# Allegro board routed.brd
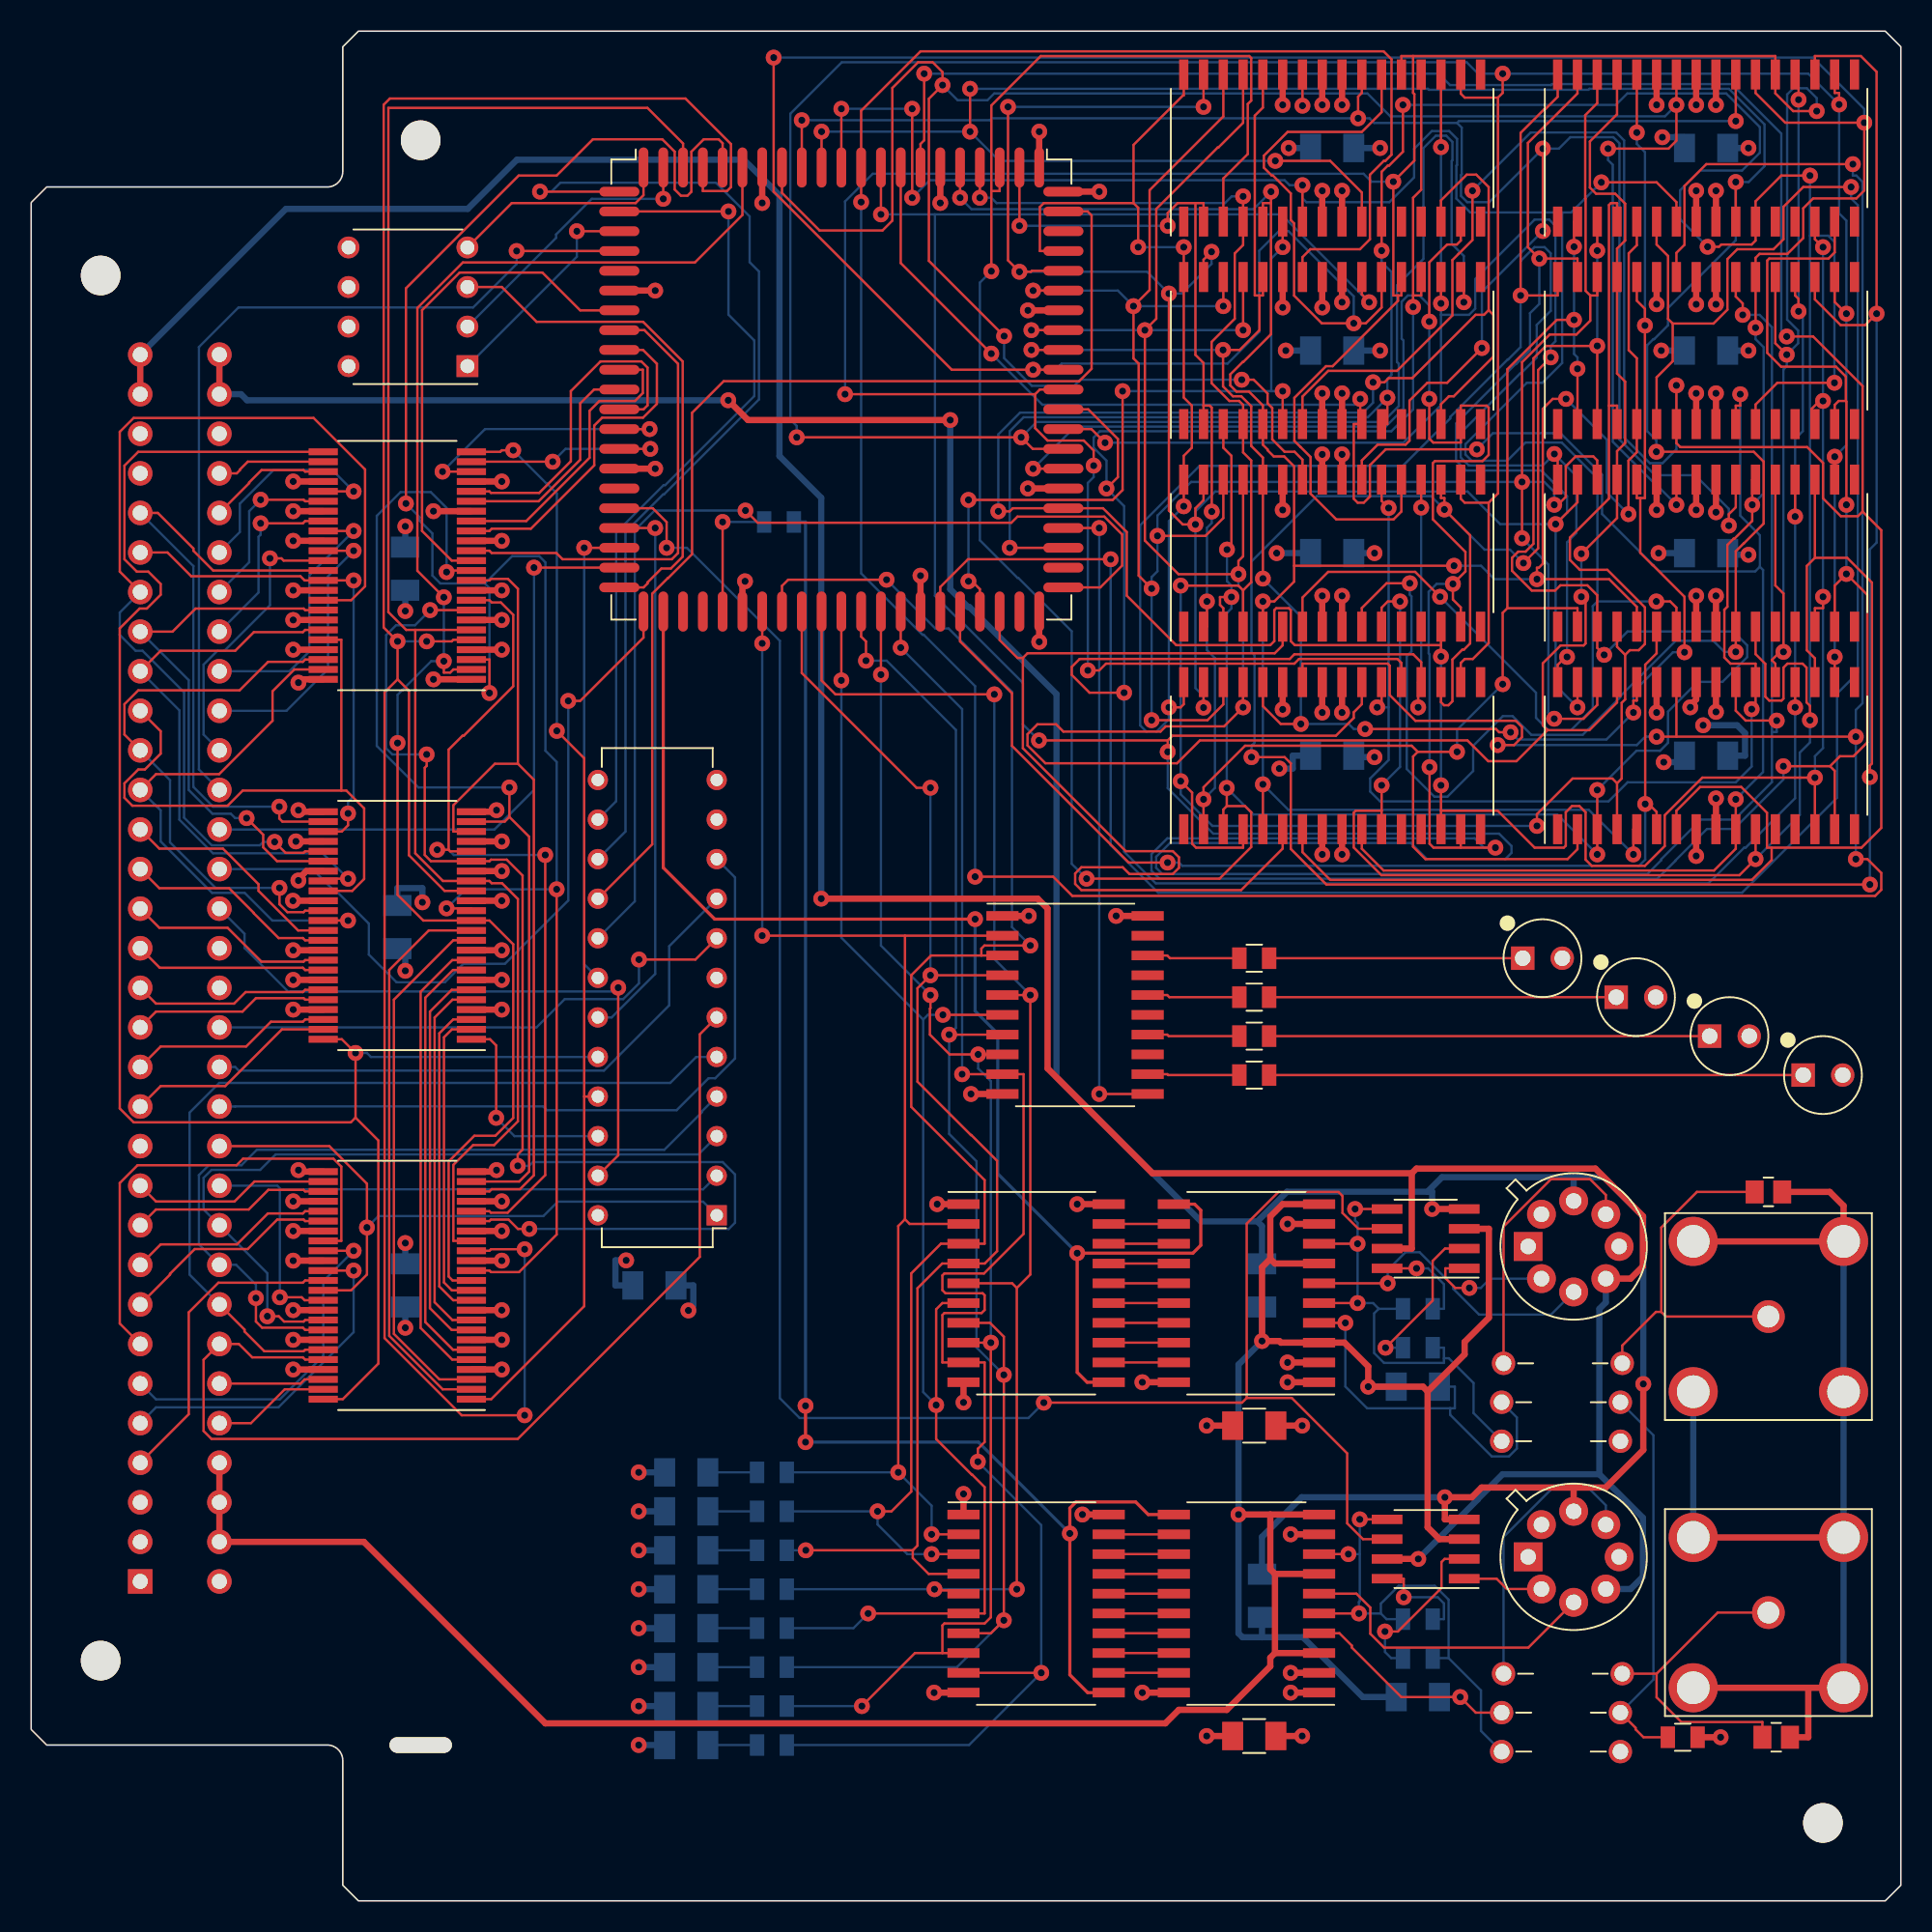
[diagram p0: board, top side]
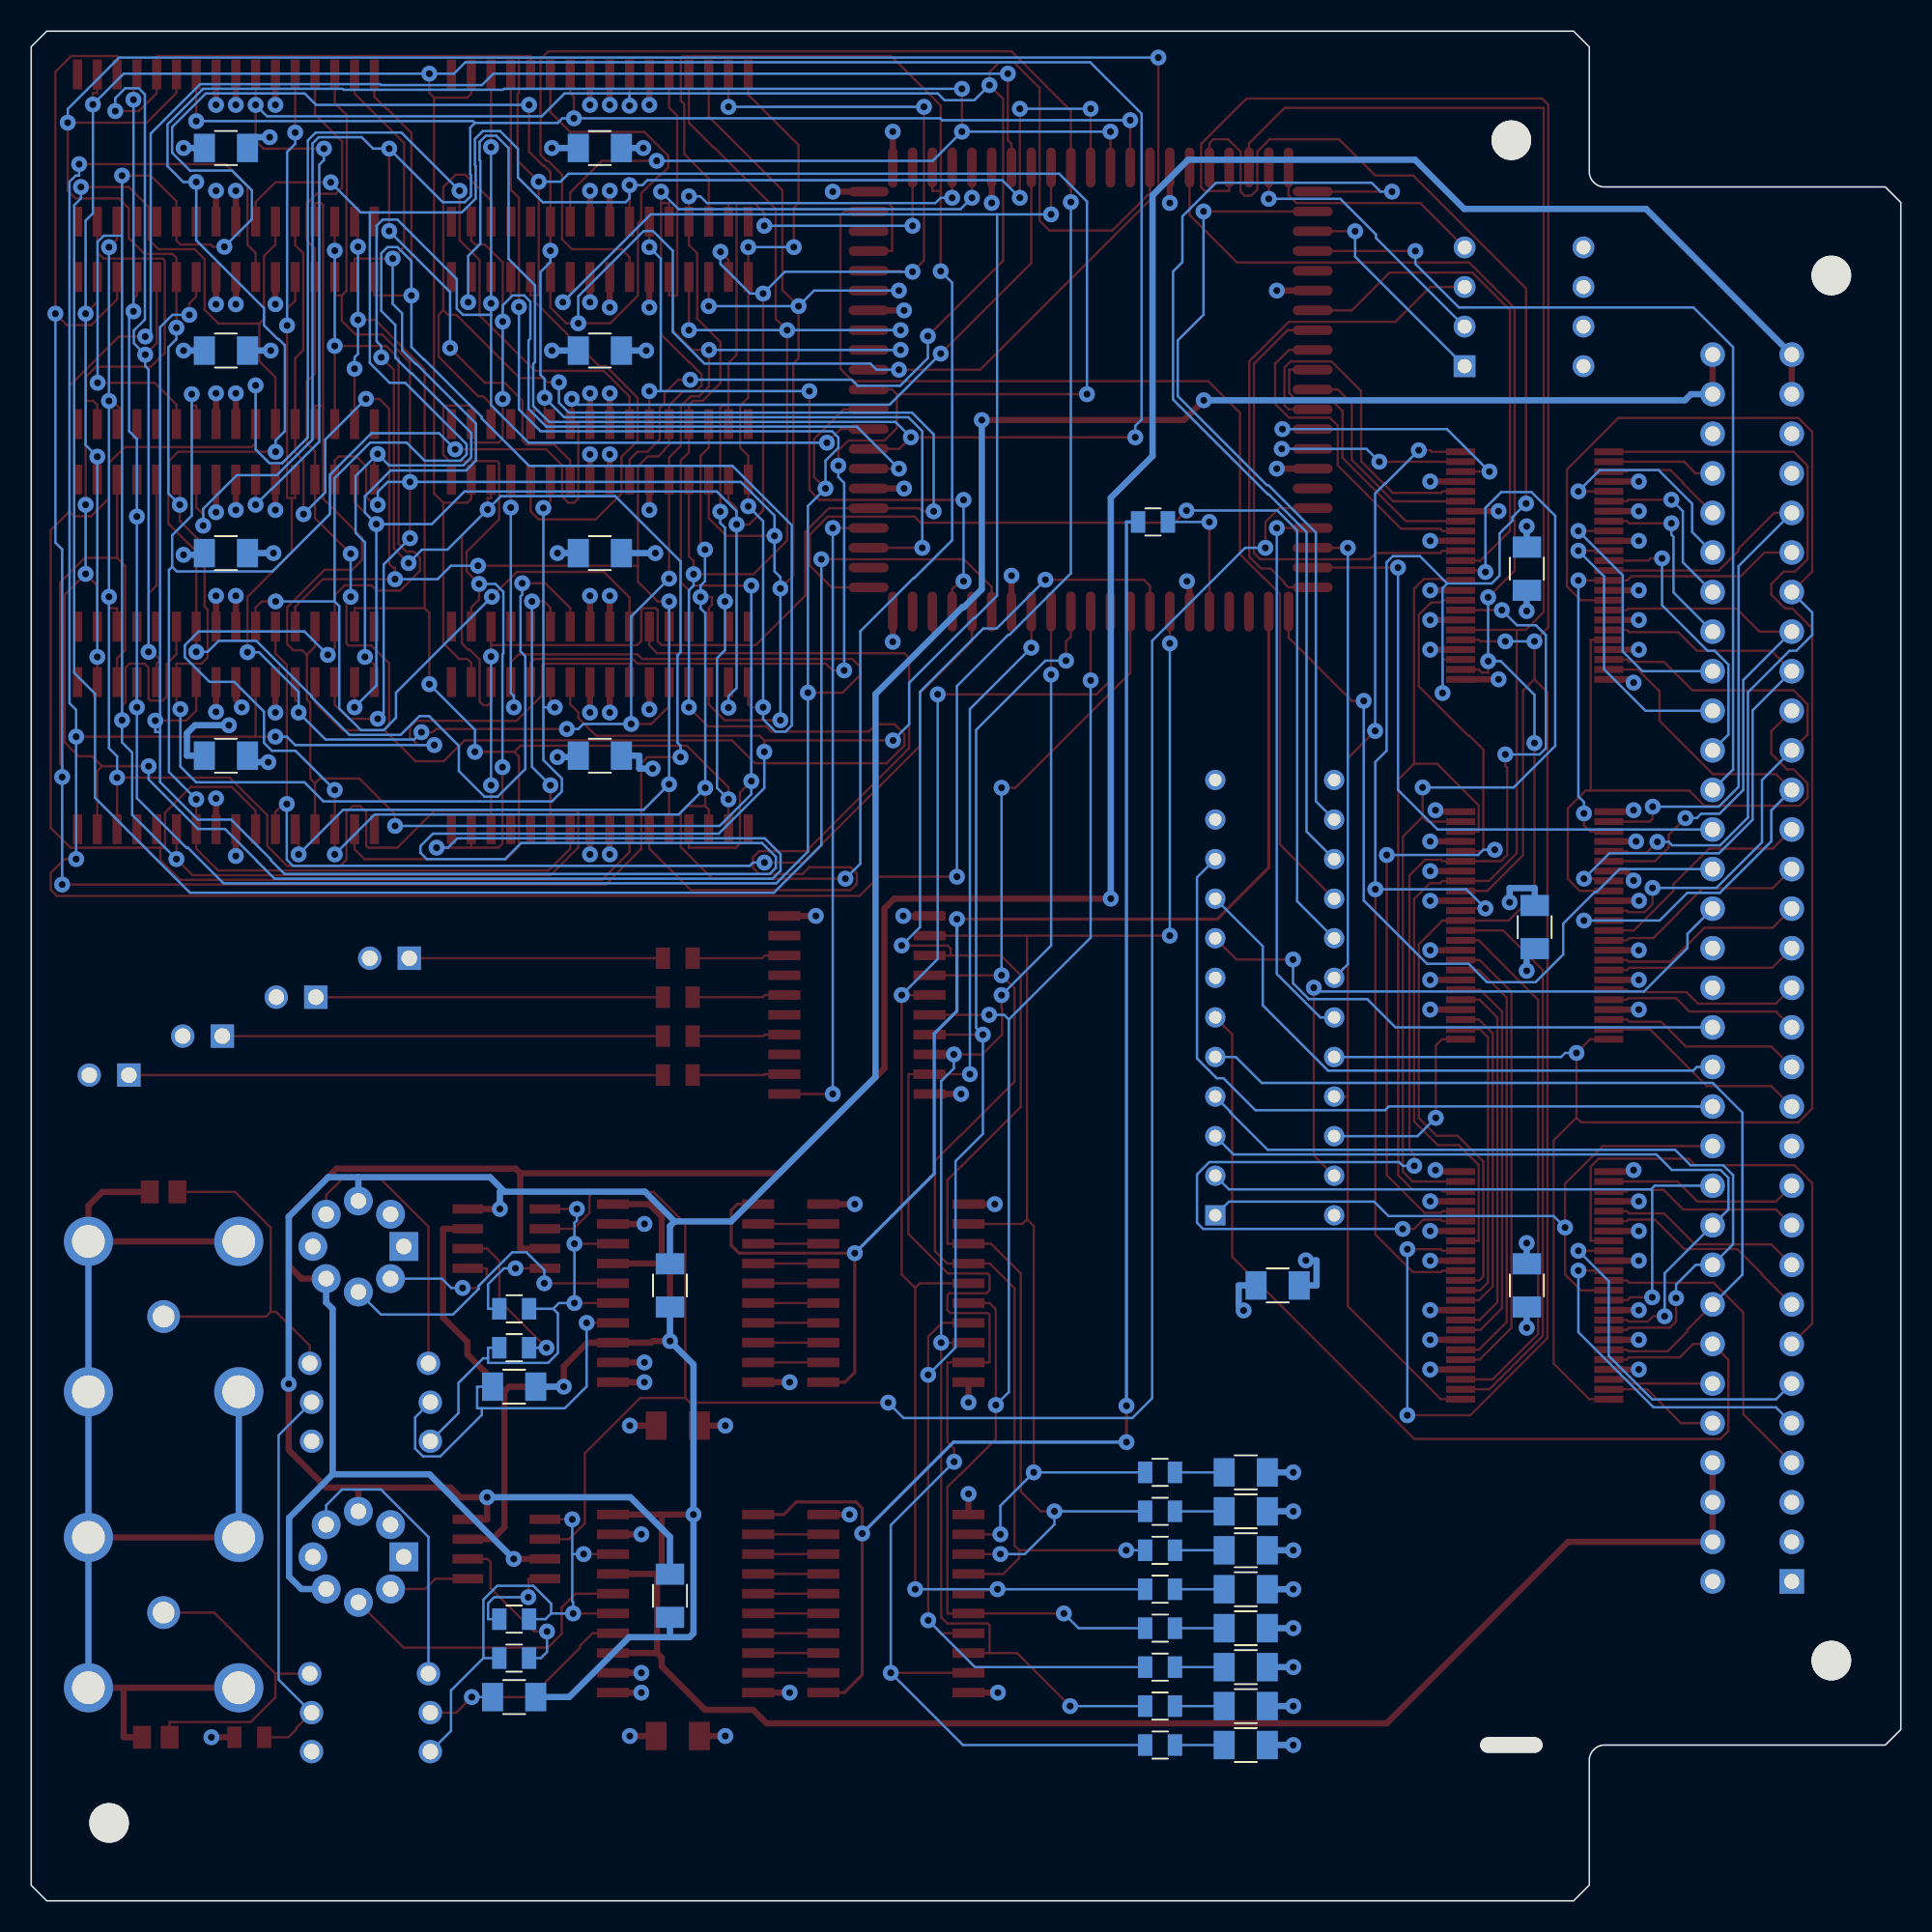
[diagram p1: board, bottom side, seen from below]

Outline 120 x 120 mm; copper layers: TOP, GND1, VCC1, VCC2, GND2, BOTTOM. Coordinates in mm from the lower left corner of the outline.

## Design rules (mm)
constraint set DEFAULT: min track width 0.15
net group SYNC: nets VCLKA VCLKC
net group MEMORY[0..28]: nets MEMORY.RA0 MEMORY.RA1 MEMORY.RA2 MEMORY.RA3 MEMORY.RA4 MEMORY.RA5 MEMORY.RA6 MEMORY.RA7 MEMORY.RA8 MEMORY.RA9 MEMORY.RA10 MEMORY.RA11 MEMORY.RA12 MEMORY.RA13 MEMORY.RA14 MEMORY.RA15 MEMORY.RCS0 MEMORY.RCS1 MEMORY.RCS2 MEMORY.RCS3 MEMORY.RD0 MEMORY.RD1 MEMORY.RD2 MEMORY.RD3 MEMORY.RD4 MEMORY.RD5 MEMORY.RD6 MEMORY.RD7 MEMORY.RWE
net group POWER: nets AGND GND_EARTH V12N V+12
net group VDNETS: nets VD0 VD1 VD2 VD3 VD4 VD5 VD6 VD7
nets with their own width: min track width 0.4; nets GND VCC

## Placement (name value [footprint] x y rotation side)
C1  0.1uF  [CAPC3216X110N]  24 39.5 90 bottom
C2  0.1uF  [CAPC3216X110N]  40 39.5 0 bottom
C3  0.1uF  [CAPC3216X110N]  23.5 62.5 90 bottom
C4  0.1uF  [CAPC3216X110N]  24 85.5 90 bottom
C5  47PF  [CAPC2012X110N]  111.5 45.5 0 top
C6  47PF  [CAPC2012X110N]  112 10.5 0 top
C7  0.01u  [CAPC3216X110N]  78.5 30.5 0 top
C8  0.01u  [CAPC3216X110N]  89 33 180 bottom
C9  0.1u  [CAPC3216X110N]  79 39.5 270 bottom
C10  0.01u  [CAPC3216X110N]  78.5 10.58 0 top
C11  0.01u  [CAPC3216X110N]  89 13.08 180 bottom
C12  0.1u  [CAPC3216X110N]  79 19.58 270 bottom
C13  330p  [CAPC3216X110N]  42.05 12.5 180 bottom
C14  330p  [CAPC3216X110N]  42.05 17.5 180 bottom
C15  330p  [CAPC3216X110N]  42.05 22.5 180 bottom
C16  330p  [CAPC3216X110N]  42.05 27.5 180 bottom
C17  330p  [CAPC3216X110N]  42.05 10 180 bottom
C18  330p  [CAPC3216X110N]  42.05 15 180 bottom
C19  330p  [CAPC3216X110N]  42.05 20 180 bottom
C20  330p  [CAPC3216X110N]  42.05 25 180 bottom
C21  0.1uF  [CAPC3216X110N]  83.5 112.5 0 bottom
C22  0.1uF  [CAPC3216X110N]  83.5 99.5 0 bottom
C23  0.1uF  [CAPC3216X110N]  83.5 86.5 0 bottom
C24  0.1uF  [CAPC3216X110N]  83.5 73.5 0 bottom
C25  0.1uF  [CAPC3216X110N]  107.5 73.5 0 bottom
C26  0.1uF  [CAPC3216X110N]  107.5 86.5 0 bottom
C27  0.1uF  [CAPC3216X110N]  107.5 112.5 0 bottom
C28  0.1uF  [CAPC3216X110N]  107.5 99.5 0 bottom
D1  LED  [LEDRD254W00D500H860P]  97 60.5 0 top
D2  LED  [LEDRD254W00D500H860P]  103 58 0 top
D3  LED  [LEDRD254W00D500H860P]  109 55.5 0 top
D4  LED  [LEDRD254W00D500H860P]  115 53 0 top
J1  CON64  [DIN64]  7 20.5 0 top
J2  BNC  [CONNEX_112659]  111.5 37.5 0 top
J3  BNC  [CONNEX_112659]  111.5 18.5 0 top
L1  47u  [INDAD762W79L381D254P]  94.5 34.5 0 top
L2  47u  [INDAD762W79L381D254P]  94.5 14.58 0 top
L3  47u  [INDAD762W79L381D254P]  102 32 180 top
L4  47u  [INDAD762W79L381D254P]  102 29.5 180 top
L5  47u  [INDAD762W79L381D254P]  102 12.08 180 top
L6  47u  [INDAD762W79L381D254P]  102 9.58 180 top
NOREF  -  []  19.76 110.35 0 top
NOREF#2  -  []  119.43 119.57 0 top
NOREF#3  -  []  25 10 90 top
NOREF#4  -  []  -71.52 -89.06 0 top
NOREF#5  -  []  20 4.47 0 top
NOREF#6  -  []  25 10 90 top
NOREF#7  -  []  25 10 0 top
NOREF#8  -  [unnamed#2]  25 10 0 top
NOREF#9  -  []  25 10 0 top
NOREF#10  -  []  0 15.3 0 top
NOREF#11  -  []  25.27 0 90 top
NOREF#12  -  []  197.72 152.24 0 top
NOREF#13  -  []  25 10 90 top
R1  150  [RESC2012X60N]  78.5 60.5 0 top
R2  150  [RESC2012X60N]  78.5 58 0 top
R3  150  [RESC2012X60N]  78.5 55.5 0 top
R4  150  [RESC2012X60N]  78.5 53 0 top
R5  2K  [RESC2012X60N]  48 88.5 0 bottom
R6  100  [RESC2012X60N]  89 38 0 bottom
R7  100  [RESC2012X60N]  89 35.5 180 bottom
R8  100  [RESC2012X60N]  89 18.08 0 bottom
R9  100  [RESC2012X60N]  89 15.58 180 bottom
R10  10K  [RESC2012X60N]  47.55 12.5 0 bottom
R11  10K  [RESC2012X60N]  47.55 17.5 0 bottom
R12  10K  [RESC2012X60N]  47.55 22.5 0 bottom
R13  10K  [RESC2012X60N]  47.55 27.5 0 bottom
R14  10K  [RESC2012X60N]  47.55 10 0 bottom
R15  10K  [RESC2012X60N]  47.55 15 0 bottom
R16  10K  [RESC2012X60N]  47.55 20 0 bottom
R17  10K  [RESC2012X60N]  47.55 25 0 bottom
R18  10K  [RESC2012X60N]  106 10.5 0 top
U1  FCT16245  [SOP63P1035X279-48N]  23.5 39.5 90 top
U2  20L10  [DIP763W46P254L3204H508Q24P]  44 44 90 top
U3  FCT16245  [SOP63P1035X279-48N]  23.5 62.6 90 top
U4  FCT16245  [SOP63P1035X279-48N]  23.5 85.7 90 top
U5  EPF8282A_LCC  [PLCC127P3022X3022X457-84N]  52 97 270 top
U6  74ACT574  [SOIC127P1034X264-20N]  67 57.5 270 top
U7  EPC1064  [DIP763W46P254L991H419Q8P]  28 98.5 90 top
U8  TLC5602A  [SOIC127P1034X264-20N]  78 39 90 top
U9  TLE2037A  [TO292P469H584-8P]  99 42 0 top
U10  DG419AK  [SOIC127P600X175-8N]  89.5 42.5 90 top
U11  TLC5602A  [SOIC127P1034X264-20N]  78 19.08 90 top
U12  TLE2037A  [TO292P469H584-8P]  99 22.08 0 top
U13  DG419AK  [SOIC127P600X175-8N]  89.5 22.58 90 top
U14  74ACT574  [SOIC127P1034X264-20N]  64.5 39 270 top
U15  74ACT574  [SOIC127P1034X264-20N]  64.5 19.08 270 top
U16  TC55B4257  [SOIC127P1032X265-32N]  83.5 73.5 0 top
U17  TC55B4257  [SOIC127P1032X265-32N]  83.5 86.5 0 top
U18  TC55B4257  [SOIC127P1032X265-32N]  83.5 99.5 0 top
U19  TC55B4257  [SOIC127P1032X265-32N]  83.5 112.5 0 top
U20  TC55B4257  [SOIC127P1032X265-32N]  107.5 73.5 0 top
U21  TC55B4257  [SOIC127P1032X265-32N]  107.5 86.5 0 top
U22  TC55B4257  [SOIC127P1032X265-32N]  107.5 99.5 0 top
U23  TC55B4257  [SOIC127P1032X265-32N]  107.5 112.5 0 top

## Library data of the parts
C1-C4 C13-C20 = CAP NP
C5 C7-C9 = CAP NP: room: CHAN1
C6 C10-C12 = CAP NP: room: CHAN2
C21-C28 = CAP NP: room: MEM
D1-D4 = PHOTODIODE_0
J1 = CON64
J2 = BNC: room: CHAN1
J3 = BNC: room: CHAN2
L1 L3 L4 = INDUCTOR: room: CHAN1
L2 L5 L6 = INDUCTOR: room: CHAN2
R1-R4 = R: room: LED
R5 R10-R17 = R
R6 R7 = R: room: CHAN1
R8 R9 R18 = R: room: CHAN2
U1 U3 U4 = FCT16245
U2 = 20L10: alternate symbols: (T:SOIC24;B:SOIC24_PE)
U5 = EPF8282A/LCC
U6 = 74ACT574: room: LED
U7 = EPC1064
U8 = TLC5602A: room: CHAN1
U9 = TLE2037A: room: CHAN1
U10 = DG419AK: room: CHAN1
U11 = TLC5602A: room: CHAN2
U12 = TLE2037A: room: CHAN2
U13 = DG419AK: room: CHAN2
U14 = 74ACT574: room: CHAN1
U15 = 74ACT574: room: CHAN2
U16-U23 = TC55B4257: room: MEM

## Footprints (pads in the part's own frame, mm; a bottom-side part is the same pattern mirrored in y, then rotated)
CAPC2012X110N
  rect 1.15x1.47 smd: 1(-0.885,0) 2(0.885,0)
CAPC3216X110N
  rect 1.35x1.82 smd: 1(-1.385,0) 2(1.385,0)
CONNEX_112659
  round 2.1 hole 1.4: 1(0,0)
  round 3.15 hole 2.1: 2(-4.825,4.825) 3(4.825,4.825) 4(4.825,-4.825) 5(-4.825,-4.825)
DIN64
  round 2.54 hole 2.794 unplated: (-2.54,83.82) (-2.54,-5.08)
  rect 1.575x1.575 hole 0.965: 1(0,0)
  round 1.575 hole 0.965: 2(0,2.54) 3(0,5.08) 4(0,7.62) 5(0,10.16) 6(0,12.7) 7(0,15.24) 8(0,17.78) 9(0,20.32) 10(0,22.86) 11(0,25.4) 12(0,27.94) 13(0,30.48) 14(0,33.02) 15(0,35.56) 16(0,38.1) 17(0,40.64) 18(0,43.18) 19(0,45.72) 20(0,48.26) 21(0,50.8) 22(0,53.34) 23(0,55.88) 24(0,58.42) 25(0,60.96) 26(0,63.5) 27(0,66.04) 28(0,68.58) 29(0,71.12) 30(0,73.66) 31(0,76.2) 32(0,78.74) 33(5.08,0) 34(5.08,2.54) 35(5.08,5.08) 36(5.08,7.62) 37(5.08,10.16) 38(5.08,12.7) 39(5.08,15.24) 40(5.08,17.78) 41(5.08,20.32) 42(5.08,22.86) 43(5.08,25.4) 44(5.08,27.94) 45(5.08,30.48) 46(5.08,33.02) 47(5.08,35.56) 48(5.08,38.1) 49(5.08,40.64) 50(5.08,43.18) 51(5.08,45.72) 52(5.08,48.26) 53(5.08,50.8) 54(5.08,53.34) 55(5.08,55.88) 56(5.08,58.42) 57(5.08,60.96) 58(5.08,63.5) 59(5.08,66.04) 60(5.08,68.58) 61(5.08,71.12) 62(5.08,73.66) 63(5.08,76.2) 64(5.08,78.74)
DIP763W46P254L991H419Q8P
  rect 1.4x1.4 hole 0.9: 1(0,0)
  round 1.4 hole 0.9: 2(2.54,0) 3(5.08,0) 4(7.62,0) 5(7.62,7.63) 6(5.08,7.63) 7(2.54,7.63) 8(0,7.63)
DIP763W46P254L3204H508Q24P
  rect 1.3x1.3 hole 0.8: 1(0,0)
  round 1.3 hole 0.8: 2(2.54,0) 3(5.08,0) 4(7.62,0) 5(10.16,0) 6(12.7,0) 7(15.24,0) 8(17.78,0) 9(20.32,0) 10(22.86,0) 11(25.4,0) 12(27.94,0) 13(27.94,7.63) 14(25.4,7.63) 15(22.86,7.63) 16(20.32,7.63) 17(17.78,7.63) 18(15.24,7.63) 19(12.7,7.63) 20(10.16,7.63) 21(7.62,7.63) 22(5.08,7.63) 23(2.54,7.63) 24(0,7.63)
INDAD762W79L381D254P
  round 1.5 hole 1: 1(0,0) 2(7.62,0)
LEDRD254W00D500H860P
  round 1.5 hole 1: A(1.27,0)
  rect 1.5x1.5 hole 1: C(-1.27,0)
PLCC127P3022X3022X457-84N
  oval 2.57x0.62 smd: 1(-14.25,0) 2(-14.25,-1.27) 3(-14.25,-2.54) 4(-14.25,-3.81) 5(-14.25,-5.08) 6(-14.25,-6.35) 7(-14.25,-7.62) 8(-14.25,-8.89) 9(-14.25,-10.16) 10(-14.25,-11.43) 11(-14.25,-12.7) 33(14.25,-12.7) 34(14.25,-11.43) 35(14.25,-10.16) 36(14.25,-8.89) 37(14.25,-7.62) 38(14.25,-6.35) 39(14.25,-5.08) 40(14.25,-3.81) 41(14.25,-2.54) 42(14.25,-1.27) 43(14.25,0) 44(14.25,1.27) 45(14.25,2.54) 46(14.25,3.81) 47(14.25,5.08) 48(14.25,6.35) 49(14.25,7.62) 50(14.25,8.89) 51(14.25,10.16) 52(14.25,11.43) 53(14.25,12.7) 75(-14.25,12.7) 76(-14.25,11.43) 77(-14.25,10.16) 78(-14.25,8.89) 79(-14.25,7.62) 80(-14.25,6.35) 81(-14.25,5.08) 82(-14.25,3.81) 83(-14.25,2.54) 84(-14.25,1.27)
  oval 0.62x2.57 smd: 12(-12.7,-14.25) 13(-11.43,-14.25) 14(-10.16,-14.25) 15(-8.89,-14.25) 16(-7.62,-14.25) 17(-6.35,-14.25) 18(-5.08,-14.25) 19(-3.81,-14.25) 20(-2.54,-14.25) 21(-1.27,-14.25) 22(0,-14.25) 23(1.27,-14.25) 24(2.54,-14.25) 25(3.81,-14.25) 26(5.08,-14.25) 27(6.35,-14.25) 28(7.62,-14.25) 29(8.89,-14.25) 30(10.16,-14.25) 31(11.43,-14.25) 32(12.7,-14.25) 54(12.7,14.25) 55(11.43,14.25) 56(10.16,14.25) 57(8.89,14.25) 58(7.62,14.25) 59(6.35,14.25) 60(5.08,14.25) 61(3.81,14.25) 62(2.54,14.25) 63(1.27,14.25) 64(0,14.25) 65(-1.27,14.25) 66(-2.54,14.25) 67(-3.81,14.25) 68(-5.08,14.25) 69(-6.35,14.25) 70(-7.62,14.25) 71(-8.89,14.25) 72(-10.16,14.25) 73(-11.43,14.25) 74(-12.7,14.25)
RESC2012X60N
  rect 0.92x1.38 smd: 1(-0.955,0) 2(0.955,0)
SOIC127P600X175-8N
  rect 0.6x1.97 smd: 1(-1.905,-2.475) 2(-0.635,-2.475) 3(0.635,-2.475) 4(1.905,-2.475) 5(1.905,2.475) 6(0.635,2.475) 7(-0.635,2.475) 8(-1.905,2.475)
SOIC127P1032X265-32N
  rect 0.59x1.92 smd: 1(-9.525,-4.72) 2(-8.255,-4.72) 3(-6.985,-4.72) 4(-5.715,-4.72) 5(-4.445,-4.72) 6(-3.175,-4.72) 7(-1.905,-4.72) 8(-0.635,-4.72) 9(0.635,-4.72) 10(1.905,-4.72) 11(3.175,-4.72) 12(4.445,-4.72) 13(5.715,-4.72) 14(6.985,-4.72) 15(8.255,-4.72) 16(9.525,-4.72) 17(9.525,4.72) 18(8.255,4.72) 19(6.985,4.72) 20(5.715,4.72) 21(4.445,4.72) 22(3.175,4.72) 23(1.905,4.72) 24(0.635,4.72) 25(-0.635,4.72) 26(-1.905,4.72) 27(-3.175,4.72) 28(-4.445,4.72) 29(-5.715,4.72) 30(-6.985,4.72) 31(-8.255,4.72) 32(-9.525,4.72)
SOIC127P1034X264-20N
  rect 0.61x2.06 smd: 1(-5.715,-4.66) 2(-4.445,-4.66) 3(-3.175,-4.66) 4(-1.905,-4.66) 5(-0.635,-4.66) 6(0.635,-4.66) 7(1.905,-4.66) 8(3.175,-4.66) 9(4.445,-4.66) 10(5.715,-4.66) 11(5.715,4.66) 12(4.445,4.66) 13(3.175,4.66) 14(1.905,4.66) 15(0.635,4.66) 16(-0.635,4.66) 17(-1.905,4.66) 18(-3.175,4.66) 19(-4.445,4.66) 20(-5.715,4.66)
SOP63P1035X279-48N
  rect 0.44x1.87 smd: 1(-7.302,-4.755) 2(-6.668,-4.755) 3(-6.032,-4.755) 4(-5.398,-4.755) 5(-4.762,-4.755) 6(-4.128,-4.755) 7(-3.492,-4.755) 8(-2.858,-4.755) 9(-2.222,-4.755) 10(-1.588,-4.755) 11(-0.952,-4.755) 12(-0.318,-4.755) 13(0.318,-4.755) 14(0.952,-4.755) 15(1.588,-4.755) 16(2.222,-4.755) 17(2.858,-4.755) 18(3.492,-4.755) 19(4.128,-4.755) 20(4.762,-4.755) 21(5.398,-4.755) 22(6.032,-4.755) 23(6.668,-4.755) 24(7.302,-4.755) 25(7.302,4.755) 26(6.668,4.755) 27(6.032,4.755) 28(5.398,4.755) 29(4.762,4.755) 30(4.128,4.755) 31(3.492,4.755) 32(2.858,4.755) 33(2.222,4.755) 34(1.588,4.755) 35(0.952,4.755) 36(0.318,4.755) 37(-0.318,4.755) 38(-0.952,4.755) 39(-1.588,4.755) 40(-2.222,4.755) 41(-2.858,4.755) 42(-3.492,4.755) 43(-4.128,4.755) 44(-4.762,4.755) 45(-5.398,4.755) 46(-6.032,4.755) 47(-6.668,4.755) 48(-7.302,4.755)
TO292P469H584-8P
  rect 1.85x1.85 hole 1: 1(-2.921,0)
  round 1.85 hole 1: 2(-2.066,-2.066) 3(0,-2.921) 4(2.066,-2.066) 5(2.921,0) 6(2.066,2.066) 7(0,2.921) 8(-2.066,2.066)
unnamed#2
  round 2.54 hole 2.794 unplated: (0,103) (90,-5)
  oval 4x1 hole 5x1.5 unplated: (0,0)

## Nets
AGND: C8.2 C9.2 C11.2 C12.2 J1.34 J1.35 J1.36 U8.3 U8.7 U8.10 U10.3 U11.3 U11.7 U11.10 U13.3
GND: C1.2 C2.2 C3.2 C4.2 C7.2 C10.2 C13.2 C14.2 C15.2 C16.2 C17.2 C18.2 C19.2 C20.2 C21.2 C22.2 C23.2 C24.2 C25.2 C26.2 C27.2 C28.2 J1.1 J1.2 J1.3 J1.33 R18.2 U1.4 U1.10 U1.15 U1.21 U1.24 U1.25(G\) U1.28 U1.34 U1.39 U1.45 U2.11 U2.12 U2.13 U3.4 U3.10 U3.15 U3.21 U3.24 U3.25(G\) U3.28 U3.34 U3.39 U3.45 U4.1 U4.4 U4.10 U4.15 U4.21 U4.28 U4.34 U4.39 U4.45 U4.48 U5.5 U5.26 U5.47 U5.53 U5.68 U5.74 U5.75 U6.1 U6.10 U7.5 U8.1 U8.20 U11.1 U11.20 U14.1 U14.10 U15.1 U15.10 U16.9 U16.25 U16.27 U17.9 U17.25 U17.27 U18.9 U18.25 U18.27 U19.9 U19.25 U19.27 U20.9 U20.25 U20.27 U21.9 U21.25 U21.27 U22.9 U22.25 U22.27 U23.9 U23.25 U23.27
GND_EARTH: C5.2 C6.2 J2.2 J2.3 J2.4 J2.5(GND5) J3.2 J3.3 J3.4 J3.5(GND5)
V12N: J1.31 J1.32 U9.4(V-) U10.7 U12.4(V-) U13.7
VCC: C1.1 C2.1 C3.1 C4.1 C7.1 C10.1 C21.1 C22.1 C23.1 C24.1 C25.1 C26.1 C27.1 C28.1 D1.A D2.A D3.A D4.A J1.29 J1.30 J1.62 L4.1 L6.1 U1.7 U1.18 U1.31 U1.42 U2.24(VCC) U3.7 U3.18 U3.31 U3.42 U4.7 U4.18 U4.31 U4.42 U5.17 U5.38 U5.59 U5.80 U6.20 U7.7 U7.8 U8.2 U8.9(VD2) U11.2 U11.9(VD2) U14.20 U15.20 U16.8 U16.24 U17.8 U17.24 U18.8 U18.24 U19.8 U19.24 U20.8 U20.24 U21.8 U21.24 U22.8 U22.24 U23.8 U23.24
A0: J1.54 U4.36
A1: J1.55 U4.35
A2: J1.56 U4.33
A3: J1.57 U4.32
A4: J1.58 U4.30
A5: J1.59 U4.29
A6: J1.60 U4.27
A7: J1.61 U4.26
A8: J1.13 U3.47
A9: J1.14 U3.46
A10: J1.15 U3.44
A11: J1.16 U3.43
A12: J1.17 U3.41
A13: J1.18 U3.40
A14: J1.19 U3.38
A15: J1.20 U3.37
A16: J1.37 U1.47
A17: J1.38 U1.46
A18: J1.39 U1.44 U2.6
A19: J1.40 U1.43 U2.5
A20: J1.41 U1.41 U2.4
A21: J1.42 U1.40 U2.3
A22: J1.43 U1.38 U2.2
A23: J1.44 U1.37 U2.1
AEN: J1.47 U2.8
BA0: U1.13 U3.13 U4.2 U5.6
BA1: U1.14 U3.14 U4.3 U5.7
BA2: U1.16 U3.16 U4.5 U5.8
BA3: U1.17 U3.17 U4.6 U5.9
BA4: U1.19 U3.19 U4.8
BA5: U1.20 U3.20 U4.9
BA6: U1.22 U3.22 U4.11
BA7: U1.23 U3.23 U4.12
BD0: U4.23 U5.25
BD1: U4.22 U5.24
BD2: U4.20 U5.23
BD3: U4.19 U5.22
BD4: U4.17 U5.21
BD5: U4.16 U5.20
BD6: U4.14 U5.19
BD7: U4.13 U5.18
BD8: U1.12 U3.2
BD9: U1.11 U3.3
BD10: U1.9 U3.5
BD11: U1.8 U3.6
BD12: U1.6 U3.8
BD13: U1.5 U3.9
BD14: U1.3 U3.11
BD15: U1.2 U3.12
BNC2: C5.1 J2.1 L1.2
BNC3: C6.1 J3.1 L2.2
BRD: U2.16 U5.73
BRESET: U2.15 U5.12
BWR: U2.17 U5.54
D0: J1.28 U3.26 U4.37
D1: J1.27 U3.27 U4.38
D2: J1.26 U3.29 U4.40
D3: J1.25 U3.30 U4.41
D4: J1.24 U3.32 U4.43
D5: J1.23 U3.33 U4.44
D6: J1.22 U3.35 U4.46
D7: J1.21 U3.36 U4.47
D8: J1.4 U1.36
D9: J1.5 U1.35
D10: J1.6 U1.33
D11: J1.7 U1.32
D12: J1.8 U1.30
D13: J1.9 U1.29
D14: J1.10 U1.27
D15: J1.11 U1.26
DATA: U5.14 U7.1
DCLK: U5.10 U7.2
DDIR: U1.48 U2.20 U3.48 U4.25(G\)
DEN: U1.1 U2.21 U4.24
DHEN: U2.22 U3.1
FPGA: U2.18 U5.30
GAIN: U5.28 U10.6 U13.6
HS: U2.19 U5.29
LED1: D1.C(CATHODE) R1.2
LED2: D2.C(CATHODE) R2.2
LED3: D3.C(CATHODE) R3.2
LED4: D4.C(CATHODE) R4.2
MCLK: J1.52 U5.31
MEMORY.RA0: U5.79 U16.5 U17.5 U18.5 U19.5 U20.5 U21.5 U22.5 U23.5
MEMORY.RA1: U5.78 U16.4 U17.4 U18.4 U19.4 U20.4 U21.4 U22.4 U23.4
MEMORY.RA2: U5.77 U16.3 U17.3 U18.3 U19.3 U20.3 U21.3 U22.3 U23.3
MEMORY.RA3: U5.76 U16.2 U17.2 U18.2 U19.2 U20.2 U21.2 U22.2 U23.2
MEMORY.RA4: U5.71 U16.32 U17.32 U18.32 U19.32 U20.32 U21.32 U22.32 U23.32
MEMORY.RA5: U5.70 U16.31 U17.31 U18.31 U19.31 U20.31 U21.31 U22.31 U23.31
MEMORY.RA6: U5.69 U16.30 U17.30 U18.30 U19.30 U20.30 U21.30 U22.30 U23.30
MEMORY.RA7: U5.67 U16.29 U17.29 U18.29 U19.29 U20.29 U21.29 U22.29 U23.29
MEMORY.RA8: U5.66 U16.28 U17.28 U18.28 U19.28 U20.28 U21.28 U22.28 U23.28
MEMORY.RA9: U5.65 U16.22 U17.22 U18.22 U19.22 U20.22 U21.22 U22.22 U23.22
MEMORY.RA10: U5.64 U16.21 U17.21 U18.21 U19.21 U20.21 U21.21 U22.21 U23.21
MEMORY.RA11: U5.63 U16.20 U17.20 U18.20 U19.20 U20.20 U21.20 U22.20 U23.20
MEMORY.RA12: U5.62 U16.19 U17.19 U18.19 U19.19 U20.19 U21.19 U22.19 U23.19
MEMORY.RA13: U5.61 U16.18 U17.18 U18.18 U19.18 U20.18 U21.18 U22.18 U23.18
MEMORY.RA14: U5.60 U16.15 U17.15 U18.15 U19.15 U20.15 U21.15 U22.15 U23.15
MEMORY.RA15: U5.58 U16.14 U17.14 U18.14 U19.14 U20.14 U21.14 U22.14 U23.14
MEMORY.RCS0: U5.51 U16.6 U17.6
MEMORY.RCS1: U5.50 U18.6 U19.6
MEMORY.RCS2: U5.49 U20.6 U21.6
MEMORY.RCS3: U5.48 U22.6 U23.6
MEMORY.RD0: U5.81 U16.7 U18.7 U20.7 U22.7
MEMORY.RD1: U5.82 U16.10 U18.10 U20.10 U22.10
MEMORY.RD2: U5.83 U16.23 U18.23 U20.23 U22.23
MEMORY.RD3: U5.84 U16.26 U18.26 U20.26 U22.26
MEMORY.RD4: U5.1 U17.7 U19.7 U21.7 U23.7
MEMORY.RD5: U5.2 U17.10 U19.10 U21.10 U23.10
MEMORY.RD6: U5.3 U17.23 U19.23 U21.23 U23.23
MEMORY.RD7: U5.4 U17.26 U19.26 U21.26 U23.26
MEMORY.RWE: U5.56 U16.11(W\E\) U17.11(W\E\) U18.11(W\E\) U19.11(W\E\) U20.11(W\E\) U21.11(W\E\) U22.11(W\E\) U23.11(W\E\)
MRD: J1.46 U2.9
MWR: J1.45 U2.10
N00036_DATA_DAAMP: L4.2 R6.1 R7.1 U8.5 U8.8 U10.5(VL)
N00036_DATA_DAAMP1: L6.2 R8.1 R9.1 U11.5 U11.8 U13.5(VL)
N00038_DATA_DAAMP: C8.1 L3.2 U8.4
N00038_DATA_DAAMP1: C11.1 L5.2 U11.4
N00044_DATA_DAAMP: U9.2 U10.1
N00044_DATA_DAAMP1: U12.2 U13.1
N00060_DATA_DAAMP: U8.6 U9.3
N00060_DATA_DAAMP1: U11.6 U12.3
N282866_DATA_DAAMP: R6.2 U10.8
N282866_DATA_DAAMP1: R8.2 U13.8
N282912_DATA_DAAMP: R7.2 U10.2
N282912_DATA_DAAMP1: R9.2 U13.2
NCS: U5.11 U7.4
OE: U5.32 U7.3(OE)
OUTA: L1.1 U9.6
OUTB: L2.1 U12.6
Q0: R1.1 U6.18
Q1: R2.1 U6.16
Q2: R3.1 U6.14
Q3: R4.1 U6.12(Q8)
RDY: J1.50 U2.23
RESET: J1.53 U5.15
SEL: U2.14 U5.13
V+12: C9.1 C12.1 J1.63 J1.64 U9.7 U10.4 U12.7 U13.4
VCLKA: U5.34 U8.11 U14.11
VCLKC: R5.2 U11.11 U15.11
VD0: R13.2 U5.39 U6.2 U14.2 U15.2
VD1: R17.2 U5.40 U6.3 U14.3 U15.3
VD2: R12.2 U5.41 U6.4 U14.4 U15.4
VD3: R16.2 U5.42 U6.5 U14.5 U15.5
VD4: R11.2 U5.43 U6.6 U14.6 U15.6
VD5: R15.2 U5.44 U6.7 U14.7 U15.7
VD6: R10.2 U5.45 U6.8 U14.8 U15.8
VD7: R14.2 U5.46(VD7) U6.9 U14.9 U15.9
VREF: L3.1 L5.1 R18.1
WAIT: J1.51 U5.33
WSTAT: U5.57 U6.11
N14843: C19.1 R16.1
N14849: C15.1 R12.1
N14853: C20.1 R17.1
N14855: C16.1 R13.1
N15143: C17.1 R14.1
N15151: C13.1 R10.1
N15155: C18.1 R15.1
N15161: C14.1 R11.1
N58063: U8.12 U14.19
N58118: U8.13 U14.18
N58173: U8.14 U14.17
N58228: U8.15 U14.16
N58283: U8.16 U14.15
N58338: U8.17 U14.14
N58393: U8.18 U14.13
N58448: U8.19 U14.12(Q8)
N58834: U11.12 U15.19
N58889: U11.13 U15.18
N58944: U11.14 U15.17
N58999: U11.15 U15.16
N59054: U11.16 U15.15
N59109: U11.17 U15.14
N59164: U11.18 U15.13
N59219: U11.19 U15.12(Q8)
N409523: R5.1 U5.37

Pads without a net: J1 12 48 49; U2 7; U5 16 27 35 36 52 55 72; U6 13 15 17 19; U7 6; U9 1 5 8; U12 1 5 8; U16 1 12 13 16 17; U17 1 12 13 16 17; U18 1 12 13 16 17; U19 1 12 13 16 17; U20 1 12 13 16 17; U21 1 12 13 16 17; U22 1 12 13 16 17; U23 1 12 13 16 17

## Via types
v1: diameter 1.016, hole 0.457, TOP to BOTTOM, 481 vias

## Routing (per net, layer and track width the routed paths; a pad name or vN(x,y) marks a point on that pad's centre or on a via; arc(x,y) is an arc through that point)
AGND: length 188.8
  TOP w0.4: 79.53,24.79 79.53,21.28 79.83,20.98 ; 79.53,24.79 v1(77.49,24.79) ; 79.53,24.79 U11.10 ; U8.7 79.83,40.91 79.53,41.2 ; J1.36 J1.35 J1.34 21.35,23.04 33,11.39 72.79,11.39 73.66,12.26 76.74,12.26 79.53,15.05 79.53,15.6 79.83,15.9 ; U11.7 79.83,20.98 ; 79.83,20.98 79.83,15.9 ; 79.83,15.9 U11.3 ; 89.63,32.7 89.33,33 v1(85.81,33) 85.81,34.3 84.29,35.83 U8.3 80.21,35.83 80.11,35.93 v1(79,35.93) 79,40.67 79.53,41.2 ; 89.63,32.7 92,35.07 92,35.87 93.56,37.43 93.56,43.13 U10.3 ; 89.63,32.7 89.63,23.98 90.39,23.21 U13.3 ; 79.53,41.2 79.53,43.92 80.32,44.72 U8.10
  BOTTOM w0.4: C11.2 85.47,13.08 81.63,16.92 79,16.92 ; 79,16.92 C12.2 ; 79,16.92 77.74,16.92 77.49,17.17 v1(77.49,24.79) 77.49,34.42 v1(79,35.93) C9.2 ; C8.2 v1(85.81,33)
GND: length 179.2
  TOP w0.4: v1(30.21,57.2) U3.4 ; v1(16.82,44.9) U1.28 ; v1(25.82,78.4) 28.25,78.4 ; v1(30.21,37.91) U1.10 ; v1(16.82,57.2) U3.45 ; U3.24 29.77,69.9 v1(29.87,70) ; v1(29.87,46.9) 29.77,46.8 U1.24 ; v1(84.13,109.76) U19.9 ; v1(80.33,89.27) U17.27 ; v1(30.21,34.1) U1.4 ; v1(46.92,108.97) U5.5 ; v1(58.15,44.72) U14.1 ; v1(64.03,63.22) U6.1 ; v1(17.15,46.9) 17.25,46.8 18.75,46.8 ; v1(82.87,92.84) U17.25 ; v1(16.82,34.1) U1.45 ; v1(40.05,91.92) U5.26 ; U20.25 106.86,77.11 106.48,76.73 v1(106.48,76.6) ; v1(80.33,76.47) U16.27 ; v1(16.82,91.1) U4.28 ; v1(80.33,115.27) U19.27 ; v1(16.82,84.11) U4.39 ; v1(104.33,115.27) U23.27 ; U4.48 17.36,78.4 v1(17.15,78.19) ; v1(17.15,70) 17.25,69.9 18.75,69.9 ; v1(30.21,41.09) U1.15 ; v1(71.32,33.28) U8.20 ; v1(104.33,76.27) U20.27 ; v1(108.14,109.76) U23.9 ; v1(59.84,31.99) U14.10 ; v1(59.84,26.12) U15.1 ; v1(16.82,87.29) U4.34 ; v1(108.43,10.5) R18.2 ; v1(108.14,70.76) U20.9 ; v1(84.13,83.76) U17.9 ; v1(104.33,102.47) U22.27 ; v1(16.8,64.19) U3.34 ; v1(30.21,91.1) U4.21 ; v1(16.82,37.91) U1.39 ; v1(82.87,115.27) U19.25 ; v1(30.21,61.01) U3.10 ; v1(30.21,87.29) U4.15 ; v1(106.86,115.27) U23.25 ; v1(30.21,80.3) U4.4 ; v1(30.21,68) U3.21 ; v1(84.13,96.76) U18.9 ; v1(30.21,84.11) U4.10 ; v1(106.86,89.27) U21.25 ; v1(104.33,89.27) U21.27 ; v1(16.82,80.3) U4.45 ; v1(16.82,61.01) U3.39 ; v1(106.86,102.47) U22.25 ; v1(81.58,30.5) C7.2 ; v1(82.87,102.27) U18.25 ; v1(82.87,76.27) U16.25 ; v1(57.95,13.36) U15.10 ; v1(30.21,44.9) U1.21 ; v1(81.58,10.58) C10.2 ; v1(63.97,102.08) U5.68 ; v1(108.14,83.76) U21.9 ; v1(16.99,68) U3.28 ; v1(80.33,102.27) U18.27 ; v1(64.7,80.81) U5.53 ; v1(60.32,51.78) U6.10 ; v1(57.08,85.05) U5.47 ; v1(16.82,41.09) U1.34 ; v1(108.14,96.76) U22.9 ; v1(68.55,109.7) U5.74 ; v1(84.13,67.16) U16.9 ; v1(64.7,113.55) U5.75 ; v1(30.21,64.19) U3.15 ; v1(80.64,33.28) U8.1 ; v1(71.32,13.36) U11.20 ; v1(80.84,13.36) U11.1
  BOTTOM w0.4: C3.2 23.5,65 25.11,65 v1(25.11,64.09) ; C26.2 108.89,86.39 v1(110.22,86.39) ; v1(38.99,22.5) C15.2 ; C25.2 110,73.5 110,74.94 109.49,75.45 v1(107.31,75.45) ; v1(38.99,20) C19.2 ; v1(38.99,25) C20.2 ; v1(110.22,99.5) C28.2 ; v1(86.58,112.5) C21.2 ; v1(38.99,27.5) C16.2 ; C24.2 84.88,73.41 v1(86.22,73.41) ; C2.2 42.5,39.5 42.5,38.21 v1(42.18,37.89) ; v1(24.01,42.22) 24.01,40.89 C1.2 ; v1(38.99,15) C18.2 ; v1(86.58,99.5) C22.2 ; v1(110.22,112.5) C27.2 ; v1(86.22,86.5) C23.2 ; v1(38.99,10) C17.2 ; v1(24.01,88.22) 24.01,86.89 C4.2 ; v1(38.99,17.5) C14.2 ; v1(38.99,12.5) C13.2
GND_EARTH: length 77.9
  TOP w0.4: 114.06,13.68 114.06,10.5 C6.2 ; 114.06,13.68 J3.4 ; 114.06,13.68 J3.5 ; J2.2 J2.3 116.33,44.61 115.44,45.5 C5.2 ; J3.3 J3.2
  BOTTOM w0.4: J2.5 J3.2 ; J3.4 J3.3 J2.4 J2.3
V12N: length 214.8
  TOP w0.4: U9.4 102.65,39.93 103.45,40.73 103.45,43.95 100.4,47 88.91,47 88.61,46.7 ; v1(50.71,64.32) 64.6,64.32 65.24,63.69 65.24,53.43 71.97,46.7 88.61,46.7 ; 88.61,46.7 88.61,41.86 U10.7 ; U13.7 v1(89.03,21.94) ; J1.31 J1.32
  BOTTOM w0.4: U9.4 101.07,38.41 100.65,37.99 100.65,27.38 ; 100.65,27.38 103.45,24.58 103.45,20.81 102.65,20.01 101.07,20.01 ; 100.65,27.38 94.44,27.38 92.85,25.79 92.85,25.77 v1(89.03,21.94) ; J1.32 16.35,108.59 28.02,108.59 31.18,111.75 45.74,111.75 48.03,109.46 48.03,92.73 50.71,90.05 v1(50.71,64.32)
VCC: length 102.5
  TOP w0.4: v1(30.21,82.21) U4.7 ; v1(80.84,23.52) U11.9 ; v1(75.45,10.58) C10.1 ; v1(80.64,43.45) U8.9 ; v1(82.87,109.76) U19.8 ; v1(106.86,67.06) U20.8 ; v1(17.15,65.49) 17.15,65.58 17.66,66.09 U3.31 ; U5.38 45.65,84.53 v1(45.82,84.69) ; v1(84.13,92.84) U17.24 ; v1(108.14,102.47) U22.24 ; v1(84.13,115.27) U19.24 ; v1(82.87,67.16) U16.8 ; v1(67.47,24.79) U15.20 ; v1(108.14,115.27) U23.24 ; v1(16.82,42.99) U1.31 ; v1(16.82,89.19) U4.31 ; v1(82.87,83.76) U17.8 ; v1(63.97,90.65) U5.59 ; v1(84.13,102.6) U18.24 ; v1(106.86,109.76) U23.8 ; v1(106.86,83.76) U21.8 ; v1(30.21,59.11) U3.7 ; v1(108.14,76.31) U20.24 ; v1(69.64,63.22) U6.20 ; v1(80.64,34.55) U8.2 ; v1(25.82,89.19) U4.18 ; v1(80.84,14.63) U11.2 ; v1(67.14,44.72) U14.20 ; v1(16.82,59.11) U3.42 ; v1(30.21,66.09) U3.18 ; v1(82.87,96.76) U18.8 ; v1(106.86,96.76) U22.8 ; v1(30.21,42.99) U1.18 ; v1(84.13,76.27) U16.24 ; v1(16.82,36.01) U1.42 ; v1(108.14,89.12) U21.24 ; v1(75.45,30.5) C7.1 ; v1(58.35,108.97) U5.80 ; v1(30.21,36.01) U1.7 ; v1(16.82,82.21) U4.42 ; v1(40.05,103.35) U5.17
  BOTTOM w0.4: v1(24.01,36.78) 24.01,38.11 C1.1 ; v1(104.78,73.08) 106.11,73.08 C25.1 ; v1(104.69,113.19) 106.11,113.19 C27.1 ; C3.1 24.01,61.12 v1(24.01,59.69) ; v1(104.62,99.5) C28.1 ; v1(80.53,99.5) C22.1 ; v1(24.01,82.78) 24.01,84.11 C4.1 ; C2.1 37.5,39.5 37.5,41.11 v1(38.19,41.11) ; v1(79.94,86.5) C23.1 ; C24.1 80.97,73.5 80.97,72.67 v1(80.11,72.67) ; v1(104.45,86.5) C26.1 ; v1(80.71,112.5) C21.1
A0: length 18.3
  TOP w0.15: U4.36 16.2,86.02 16.06,86.16 v1(15.33,86.16)
  BOTTOM w0.15: J1.54 11.07,74.85 11.07,79.34 11.96,80.23 12.4,80.23 15.33,83.15 v1(15.33,86.16)
A1: length 18.3
  TOP w0.15: U4.35 v1(20.7,86.65)
  BOTTOM w0.15: v1(20.7,86.65) 19.05,85.01 19.05,79.05 16.38,76.38 J1.55
A2: length 17.2
  TOP w0.15: U4.33 v1(20.7,87.92)
  BOTTOM w0.15: v1(20.7,87.92) 17.85,85.08 17.85,80.19 16.58,78.92 J1.56
A3: length 12.1
  TOP w0.15: v1(14.73,88.41) 17.44,88.41 17.59,88.56 U4.32
  BOTTOM w0.15: v1(14.73,88.41) 14.73,87.68 14.59,87.55 14.59,83.97 J1.57
A4: length 11.1
  TOP w0.15: v1(14.73,89.92) 17.49,89.92 17.59,89.83 U4.30
  BOTTOM w0.15: J1.58 13.99,85.91 13.99,89.19 v1(14.73,89.92)
A5: length 14.4
  TOP w0.15: U4.29 v1(20.7,90.46)
  BOTTOM w0.15: J1.59 13.39,87.85 13.39,89.67 15.55,91.83 19.33,91.83 v1(20.7,90.46)
A6: length 7.9
  TOP w0.15: J1.60 13.99,90.99 13.99,91.04 14.79,91.83 17.49,91.83 17.59,91.73 18.75,91.73
A7: length 7
  TOP w0.15: 18.75,92.37 13.9,92.37 13.39,91.86 13.39,91.82 13.19,91.62 J1.61
A8: length 13.8
  TOP w0.15: J1.13 8.31,52.29 12.45,52.29 16.09,55.93 U3.47
A9: length 13
  TOP w0.15: J1.14 8.31,54.83 13.8,54.83 15.39,56.42 17.44,56.42 17.59,56.57 U3.46
A10: length 12.6
  TOP w0.15: J1.15 8.01,57.07 13.56,57.07 14.42,57.94 17.49,57.94 17.59,57.84 U3.44
A11: length 12.5
  TOP w0.15: J1.16 8.01,57.59 13.02,57.59 13.76,58.33 17.44,58.33 17.59,58.47 U3.43
A12: length 12.3
  TOP w0.15: J1.17 8.25,59.89 17.44,59.89 17.59,59.74 U3.41
A13: length 13.2
  TOP w0.15: U3.40 17.59,60.38 17.49,60.28 14.78,60.28 12.61,62.45 8.23,62.45 J1.18
A14: length 13.7
  TOP w0.15: U3.38 17.59,61.65 17.44,61.79 15.88,61.79 14.29,63.38 14.29,63.41 12.71,64.99 8.23,64.99 J1.19
A15: length 14.7
  TOP w0.15: U3.37 17.13,62.28 14.59,64.82 14.59,65.25 12.31,67.53 8.23,67.53 J1.20
A16: length 7.6
  TOP w0.15: U1.47 16.28,32.83 14.11,30.66 J1.37
A17: length 6.8
  TOP w0.15: U1.46 17.55,33.47 17.28,33.2 J1.38
A18: length 65.8
  TOP w0.15: U2.6 42.91,55.62 42.91,41.33 31.23,29.65 11.57,29.65 11.07,30.16 11.07,34.73 J1.39 13.33,35.74 14.19,34.88 17.44,34.88 17.59,34.74 U1.44
A19: length 56.4
  TOP w0.15: U1.43 17.59,35.37 17.49,35.27 14.96,35.27 13.69,36.55 13.69,36.67 J1.40
  BOTTOM w0.15: U2.5 42.68,54.16 41.02,52.5 12.07,52.5 10.17,50.59 10.17,40.19 J1.40
A20: length 51.4
  TOP w0.15: U1.41 17.59,36.64 17.44,36.79 14.82,36.79 14.43,37.18 v1(14.43,38.69)
  BOTTOM w0.15: U2.4 43.05,50.67 43.05,50.62 40.64,48.2 14.49,48.2 13.5,47.21 11.4,47.21 10.77,46.58 10.77,42.13 J1.41 13.16,40.82 14.43,39.55 v1(14.43,38.69)
A21: length 48.4
  TOP w0.15: U1.40 17.59,37.28 17.49,37.18 16.23,37.18 15.89,37.52 v1(15.16,37.52)
  BOTTOM w0.15: v1(15.16,37.52) 15.16,40.28 J1.42 11.07,44.37 11.07,46.41 11.57,46.91 14.7,46.91 15.69,47.91 42.83,47.91 U2.3
A22: length 42.2
  TOP w0.15: v1(15.96,38.74) 17.36,38.74 17.55,38.55 U1.38
  BOTTOM w0.15: 16.03,45.66 15.8,45.9 J1.43 ; 16.03,45.66 15.96,45.59 v1(15.96,38.74) ; 16.03,45.66 43.12,45.66 U2.2
A23: length 43
  TOP w0.15: J1.44 19.14,48.44 21.55,46.03 v1(21.55,43.22) 21.55,40.2 20.54,39.18 U1.37
  BOTTOM w0.15: U2.1 43.12,44.88 33.8,44.88 32.88,43.95 22.28,43.95 v1(21.55,43.22)
AEN: length 35.2
  TOP w0.15: v1(39.01,60.41) 42.64,60.41 U2.8
  BOTTOM w0.15: J1.47 32.43,56.06 34.25,57.88 37.99,57.88 39.01,58.89 v1(39.01,60.41)
BA0: length 103.2
  TOP w0.15: v1(26.49,83.67) 24.79,85.37 24.79,102.23 27.71,105.16 42.6,105.16 45.65,108.2 U5.6 ; v1(23.52,74.31) 23.52,64.57 25.17,62.92 U3.13 29.42,62.92 30.94,61.39 30.94,50.25 29.8,49.1 28.45,49.1 26.8,47.45 26.8,40.07 27.05,39.82 U1.13 ; v1(26.49,79.56) 26.49,78.83 26.89,78.83 27.09,79.03 28.25,79.03
  BOTTOM w0.15: v1(23.52,74.31) 23.52,77.41 25.68,79.56 v1(26.49,79.56) v1(26.49,83.67)
BA1: length 129.1
  TOP w0.15: v1(26.66,63.7) 28.25,63.7 U3.14 ; v1(29.41,77.52) 29.41,79.67 28.25,79.67 ; v1(24.05,89.68) 24.05,103.49 31.29,110.73 33.73,110.73 36.05,113.06 40.51,113.06 41.3,112.27 41.3,109.84 41.7,109.44 42.12,109.44 42.38,109.69 42.38,112.27 43.17,113.06 44.13,113.06 44.38,112.81 U5.7 ; v1(33.73,64.92) 33.73,42.77 31.32,40.36 29.51,40.36 29.41,40.45 U1.14
  BOTTOM w0.15: 29.12,84.55 30.87,86.3 32.61,86.3 33.01,85.91 33.01,73.82 33.73,73.1 v1(33.73,64.92) 27.89,64.92 v1(26.66,63.7) ; 29.12,84.55 26.26,84.55 25.75,85.06 25.75,87.76 24.93,88.59 24.93,88.81 v1(24.05,89.68) ; 29.12,84.55 29.41,84.25 v1(29.41,77.52)
BA2: length 156.2
  TOP w0.15: U4.5 27.09,80.94 26.99,80.84 v1(25.39,80.84) ; U3.16 26.54,64.82 24.25,67.11 24.25,77.67 23.52,78.4 ; U1.16 29.41,41.72 29.51,41.82 v1(31.67,41.82) ; v1(31.67,31.16) 27.63,31.16 22.68,36.12 22.68,77.56 23.52,78.4 ; 23.52,78.4 v1(23.52,80.84) 22.62,81.73 22.62,115.28 23.02,115.67 41.99,115.67 44.91,112.75 44.91,109.99 44.66,109.74 43.11,109.74 U5.8
  BOTTOM w0.15: v1(25.39,80.84) v1(23.52,80.84) ; v1(31.67,41.82) v1(31.67,31.16)
BA3: length 107.3
  TOP w0.15: U5.9 41.84,112.79 39.55,115.08 22.93,115.08 22.93,82.72 24.07,81.57 24.65,81.57 ; U1.17 27.09,42.36 27.09,47.23 28.37,48.51 29.72,48.51 31.24,50.03 31.24,64.3 30.22,65.31 29.56,65.31 29.41,65.46 U3.17 26.43,65.46 24.65,67.24 24.65,81.57 ; U4.6 24.65,81.57
BA4: length 83.2
  TOP w0.15: U1.19 29.41,43.63 29.51,43.73 30.64,43.73 31.24,43.12 v1(31.97,43.12) ; v1(25.39,73.58) 25.39,72.85 25.26,72.72 25.26,67.12 25.66,66.73 U3.19 29.41,66.73 29.51,66.83 30.52,66.83 31.54,65.81 31.54,48.22 31.23,47.91 v1(31.23,47.17) ; U4.8 v1(25.61,82.84)
  BOTTOM w0.15: v1(31.97,43.12) 44.78,43.12 45.17,43.52 45.17,46.62 44.38,47.41 32.2,47.41 31.96,47.17 v1(31.23,47.17) ; v1(25.61,82.84) 24.64,81.87 23.42,81.87 22.78,81.23 22.78,73.98 23.18,73.58 v1(25.39,73.58)
BA5: length 55.5
  TOP w0.15: 26.8,67.46 v1(26.06,67.46) ; 26.8,67.46 26.89,67.36 U3.20 ; 26.8,67.46 26.8,73.89 27.68,74.78 27.77,74.78 30.94,77.95 30.94,82.54 30.15,83.33 29.56,83.33 29.41,83.48 U4.9 ; v1(32.99,67.12) 32.99,46.58 30.58,44.16 29.51,44.16 29.41,44.26 U1.20
  BOTTOM w0.15: v1(26.06,67.46) 26.8,67.46 27.13,67.12 v1(32.99,67.12)
BA6: length 53.9
  TOP w0.15: 31.24,72.98 31.24,84.21 30.61,84.84 29.51,84.84 29.41,84.75 U4.11 ; 31.24,72.98 29.76,72.98 27.09,70.31 27.09,68.63 U3.22 ; 31.24,72.98 32.26,71.96 32.26,46.57 31.37,45.68 29.56,45.68 29.41,45.53 U1.22
BA7: length 67.4
  TOP w0.15: v1(30.69,71.46) 30.69,69.57 ; 30.69,69.57 31.96,68.3 31.96,46.8 31.33,46.17 U1.23 ; 30.69,69.57 30.39,69.27 U3.23 ; v1(26.66,85.28) 26.76,85.38 U4.12
  BOTTOM w0.15: v1(26.66,85.28) 26.66,89.4 25.65,90.42 23.71,90.42 22.18,88.89 22.18,74.13 24.85,71.46 v1(30.69,71.46)
BD0: length 13.8
  TOP w0.15: U4.23 v1(33.47,92.37) ; U5.25 v1(39.74,93.19)
  BOTTOM w0.15: v1(33.47,92.37) 34.3,93.19 v1(39.74,93.19)
BD1: length 18.2
  TOP w0.15: U4.22 v1(26.4,91.73) ; U5.24 v1(39.69,94.46)
  BOTTOM w0.15: v1(39.69,94.46) 29.13,94.46 v1(26.4,91.73)
BD2: length 22
  TOP w0.15: U5.23 39.31,95.73 39.56,95.98 39.56,98.41 39.16,98.81 36.54,98.81 34.64,96.9 34.64,92.4 32.61,90.36 29.51,90.36 29.41,90.46 U4.20
BD3: length 14.6
  TOP w0.15: U5.22 36.13,97 35.24,96.11 35.24,92.5 32.57,89.83 U4.19
BD4: length 19.2
  TOP w0.15: U4.17 31.77,88.56 35.84,92.62 35.84,95.63 36.47,96.27 38.75,96.27 39.26,96.77 39.26,98.27 U5.21
BD5: length 22.1
  TOP w0.15: U5.20 39.27,99.54 40.16,98.65 40.16,96.08 39.27,95.19 36.65,95.19 36.14,94.69 36.14,92.13 32.08,88.07 29.56,88.07 29.41,87.92 U4.16
BD6: length 30.5
  TOP w0.15: U4.14 29.41,86.65 29.56,86.51 33.71,86.51 34.11,86.11 41.12,86.11 41.52,86.5 41.52,98.65 39.36,100.81 U5.19
BD7: length 32.8
  TOP w0.15: U5.18 35.24,102.08 32.81,104.5 27.5,104.5 25.09,102.09 25.09,87.92 26.99,86.02 U4.13
BD8: length 19.7
  TOP w0.15: U1.12 27,39.18 26.5,39.69 26.5,55.42 27,55.93 28.25,55.93
BD9: length 21.1
  TOP w0.15: 28.25,56.57 27.08,56.57 26.2,55.68 26.2,39.44 27.08,38.55 U1.11
BD10: length 23.9
  TOP w0.15: U1.9 27.04,37.28 25.89,38.42 25.89,56.7 27.04,57.84 U3.5
BD11: length 25.5
  TOP w0.15: U1.8 26.99,36.64 25.59,38.04 25.59,57.08 26.99,58.47 U3.6
BD12: length 28.2
  TOP w0.15: U1.6 27.07,35.37 25.3,37.15 25.3,57.96 27.07,59.74 U3.8
BD13: length 29.8
  TOP w0.15: U1.5 27.03,34.74 25,36.77 25,58.35 27.03,60.38 U3.9
BD14: length 34.2
  TOP w0.15: U3.11 27.09,61.65 23.28,57.84 23.28,36.39 26.2,33.47 28.25,33.47
BD15: length 36.5
  TOP w0.15: U3.12 25.52,62.28 22.98,59.74 22.98,36.26 26.41,32.83 28.25,32.83
BNC2: length 23.9
  TOP w0.15: J2.1 104.92,37.5 104.62,37.8 ; 104.62,37.8 104.28,37.8 102.12,35.64 L1.2 ; 104.62,37.8 104.62,43.21 106.91,45.5 C5.1
BNC3: length 20.9
  TOP w0.15: L2.2 104.33,14.58 ; 104.33,14.58 104.33,13.06 105.91,11.47 111.11,11.47 C6.1 ; 104.33,14.58 108.25,18.5 J3.1
BRD: length 72.3
  TOP w0.15: U5.73 67.81,108.43 68.06,108.18 68.06,98.33 67.27,97.54 44.45,97.54 42.42,95.5 42.42,86.43 40.89,84.91 40.88,84.91 39.86,83.89 39.86,67.81 U2.16
BRESET: length 65.5
  TOP w0.15: U5.12 v1(32.66,109.7)
  BOTTOM w0.15: U2.15 38.14,68.63 38.14,87.85 40.56,90.27 40.62,90.27 46.71,96.36 46.71,104.58 46.11,105.17 46.11,108.11 43.95,110.27 33.96,110.27 33.39,109.7 v1(32.66,109.7)
BWR: length 66.3
  TOP w0.15: v1(45.85,89.23) 46.63,88.45 62.91,88.45 63.3,88.84 68.88,88.84 70.02,87.7 70.02,85.7 68.62,84.3 U5.54
  BOTTOM w0.15: v1(45.85,89.23) 40.02,89.23 38.74,87.96 38.74,64.16 U2.17
D0: length 42.1
  TOP w0.15: v1(15.93,70.23) 15.93,69.47 16.12,69.27 18.75,69.27 ; U4.37 11.68,85.38 10.41,86.65 10.41,86.79 8.13,89.08 J1.28
  BOTTOM w0.15: J1.28 10.41,85.67 10.41,71.5 11.68,70.23 v1(15.93,70.23)
D1: length 32.1
  TOP w0.15: J1.27 8.75,86.54 10.28,85.01 17.29,85.01 17.55,84.75 U4.38 v1(20.7,84.75) ; v1(20.34,69.79) 20.34,69.03 19.94,68.63 18.75,68.63
  BOTTOM w0.15: v1(20.34,69.79) 20.34,70.53 20.7,70.88 v1(20.7,84.75)
D2: length 65.9
  TOP w0.15: U4.40 20.54,83.48 21.43,84.37 21.43,91.87 18.13,95.17 6.58,95.17 5.69,94.28 5.69,85.31 J1.26 ; U3.29 17.59,67.36 17.49,67.27 16.33,67.27 v1(15.63,67.97)
  BOTTOM w0.15: J1.26 5.69,82.69 5.69,81.25 6.7,80.23 7.15,80.23 9.81,77.57 9.81,69.53 11.59,67.75 14.67,67.75 14.89,67.97 v1(15.63,67.97)
D3: length 34.9
  TOP w0.15: J1.25 9.07,81.46 10.55,82.94 17.49,82.94 17.59,82.84 U4.41 ; U3.30 15.78,66.73 14.89,67.62 14.89,68.43 v1(13.83,69.49)
  BOTTOM w0.15: v1(13.83,69.49) 13.09,69.49 12.81,69.77 11.64,69.77 10.11,71.3 10.11,78.35 J1.25
D4: length 37.5
  TOP w0.15: U3.32 18.75,65.6 v1(20.34,65.6) ; J1.24 8.31,80.23 13.1,80.23 14.29,81.43 17.44,81.43 17.59,81.57 U4.43
  BOTTOM w0.15: v1(20.34,65.6) 18.71,67.23 11.67,67.23 9.51,69.39 9.51,76.41 J1.24
D5: length 42.1
  TOP w0.15: 19.91,71.26 13.58,71.26 12.61,70.29 6.5,70.29 5.99,70.8 5.99,71.72 6.88,72.61 7.3,72.61 8.31,73.63 8.31,75.07 J1.23 ; 19.91,71.26 20.23,71.26 21.37,70.12 21.37,65.58 20.61,64.82 U3.33 ; 19.91,71.26 19.91,80.94 U4.44
D6: length 36.4
  TOP w0.15: v1(15.94,65.01) 15.94,63.96 16.45,63.45 17.49,63.45 17.59,63.55 U3.35 ; U4.46 17.59,79.67 17.44,79.52 15.21,79.52 13.38,77.69 6.88,77.69 5.99,76.8 5.99,74.85 J1.22
  BOTTOM w0.15: v1(15.94,65.01) 11.83,65.01 8.91,67.93 8.91,71.93 J1.22
D7: length 35.6
  TOP w0.15: U4.47 16.89,79.03 15.49,77.64 15.49,75.74 12.06,72.31 8.01,72.31 J1.21 ; U3.36 v1(20.34,62.92)
  BOTTOM w0.15: J1.21 8.31,69.99 8.31,68 11.62,64.69 13.71,64.69 15.48,62.92 v1(20.34,62.92)
D8: length 20.4
  TOP w0.15: J1.4 10.11,31.23 10.11,37.77 12.02,39.67 17.44,39.67 17.59,39.82 U1.36
D9: length 22
  TOP w0.15: U1.35 v1(20.7,40.45)
  BOTTOM w0.15: v1(20.7,40.45) 20.7,36.5 15.87,31.67 8.01,31.67 J1.5
D10: length 22.8
  TOP w0.15: U1.33 v1(20.7,41.72)
  BOTTOM w0.15: J1.6 8.01,32.19 15.96,32.19 18.75,34.98 18.75,39.78 v1(20.7,41.72)
D11: length 31.9
  TOP w0.15: U1.32 19.91,42.36 19.91,47.13 19.4,47.63 13.6,47.63 13.18,47.21 6.83,47.21 5.69,46.07 5.69,37.05 J1.7
D12: length 14.1
  TOP w0.15: J1.8 8.91,40.19 8.91,40.25 10.5,41.83 13.9,41.83 15.79,43.73 17.49,43.73 17.59,43.63 U1.30
D13: length 13.2
  TOP w0.15: U1.29 17.59,44.26 17.44,44.12 15.19,44.12 13.21,42.13 8.31,42.13 J1.9
D14: length 12.7
  TOP w0.15: J1.10 8.01,44.37 13.96,44.37 15.22,45.63 17.49,45.63 17.59,45.53 18.75,45.53
D15: length 12.7
  TOP w0.15: 18.75,46.17 14.33,46.17 13.05,44.89 8.01,44.89 J1.11
DATA: length 14.3
  TOP w0.15: U5.14 v1(35.02,107.16)
  BOTTOM w0.15: v1(35.02,107.16) 35.02,105.52 U7.1
DCLK: length 18.1
  TOP w0.15: U5.10 v1(40.57,109.24)
  BOTTOM w0.15: U7.2 33.69,106.73 33.69,106.95 35.98,109.24 v1(40.57,109.24)
DDIR: length 115.9
  TOP w0.15: 20.82,50.27 v1(20.82,54.42) 19.94,55.3 U3.48 ; 20.82,50.27 22.28,48.8 22.28,34.48 20,32.2 U1.48 ; 20.82,50.27 20.52,49.97 6.58,49.97 5.69,50.86 5.69,81.67 6.96,82.94 7.42,82.94 8.31,83.83 8.31,84.52 7.52,85.31 6.78,85.31 5.99,86.11 5.99,92.11 6.88,93 18.75,93
  BOTTOM w0.15: U2.20 21.81,54.16 21.55,54.42 v1(20.82,54.42)
DEN: length 70.2
  TOP w0.15: 35.49,51.62 35.49,73.33 v1(33.74,75.09) ; 35.49,51.62 U2.21 ; 35.49,51.62 35.49,38.17 29.53,32.2 28.25,32.2 ; v1(30.94,93.1) 30.21,93.1 30.11,93 U4.24
  BOTTOM w0.15: v1(33.74,75.09) 33.74,90.33 33.1,90.97 33.08,90.97 v1(30.94,93.1)
DHEN: length 13.4
  TOP w0.15: v1(29.85,50.26) 29.85,54.9 29.45,55.3 28.25,55.3
  BOTTOM w0.15: v1(29.85,50.26) 31.02,49.08 U2.22
FPGA: length 30.2
  TOP w0.15: U5.30 v1(35.49,86.84)
  BOTTOM w0.15: v1(35.49,86.84) 35.49,60.12 U2.18
GAIN: length 132.5
  TOP w0.15: v1(40.78,86.84) 40.78,88.49 39.9,89.38 U5.28 ; 78.02,32.27 78.02,43.46 80.05,45.49 83.91,45.49 84.16,45.24 84.16,44.15 85.18,43.13 U10.6 ; 78.02,32.27 80.91,32.27 84.47,28.72 84.47,24.23 85.48,23.21 U13.6 ; 78.02,32.27 77.72,31.98 v1(64.99,31.98)
  BOTTOM w0.15: v1(40.78,86.84) 42.08,86.84 48.05,80.87 48.05,32.26 49.32,30.99 64.01,30.99 v1(64.99,31.98)
HS: length 35.8
  TOP w0.15: U5.29 v1(40.05,88.11)
  BOTTOM w0.15: U2.19 37.26,56.7 40.05,59.49 v1(40.05,88.11)
LED1: length 16.3
  TOP w0.15: D1.C R1.2
LED2: length 22.3
  TOP w0.15: D2.C R2.2
LED3: length 28.3
  TOP w0.15: D3.C R3.2
LED4: length 34.3
  TOP w0.15: D4.C R4.2
MCLK: length 41
  TOP w0.15: U5.31 v1(32.27,85.57)
  BOTTOM w0.15: J1.52 29.73,68.76 32.27,71.3 v1(32.27,85.57)
MEMORY.RA0: length 165.1
  TOP w0.15: 79.06,83.4 79.79,83.4 81.06,84.67 81.06,85.69 ; 79.06,83.4 U17.5 ; 79.06,83.4 v1(79.05,83.4) ; U16.5 v1(79.06,71.66) ; 79.58,108.97 79.58,100.55 77.8,98.77 77.76,98.77 76.96,97.97 76.96,97.26 77.36,96.86 78.17,96.86 79.06,95.98 U18.5 79.06,93.45 79.35,93.16 79.35,93.1 79.75,92.7 80.42,92.7 81.06,92.07 81.06,85.69 ; 79.58,108.97 79.06,108.97 U19.5 ; 79.58,108.97 v1(79.58,109.7) ; v1(102.52,89) 102.52,92.44 103.06,92.97 U22.5 103.06,99 102.53,99.53 102.53,105.75 103.06,106.27 U23.5 ; v1(98.51,96.4) 97.66,96.4 97.02,95.76 97.02,85.81 96.77,85.56 96.64,85.56 v1(96.64,84.83) 101.28,84.83 103.06,83.05 U21.5 ; 81.06,85.69 v1(91.32,85.69) ; v1(102.83,67.16) 102.83,68.78 U20.5 ; v1(59.62,109.31) U5.79
  BOTTOM w0.15: v1(102.52,89) 101.13,90.39 101.13,93.78 v1(98.51,96.4) ; v1(91.32,85.69) 93.06,85.69 93.92,84.83 v1(96.64,84.83) ; v1(79.05,83.4) 79.05,82.67 79.06,82.66 v1(79.06,71.66) 80.69,70.02 99.97,70.02 v1(102.83,67.16) ; v1(79.58,109.7) 78.45,108.57 60.35,108.57 v1(59.62,109.31)
MEMORY.RA1: length 157
  TOP w0.15: U23.4 101.78,108.97 101.39,108.97 101.27,108.84 101.27,95.97 ; U5.78 v1(60.89,109.31) ; U17.4 77.78,84.11 ; 77.78,84.11 78.31,84.63 78.31,92.44 77.78,92.97 U18.4 77.78,96.01 77.53,96.27 76.91,96.27 75.76,97.41 75.76,100.06 77.25,101.54 77.25,105.74 77.78,106.27 U19.4 v1(77.78,109.4) ; 77.78,84.11 77.48,84.41 v1(73.78,84.41) ; 101.78,71.73 102.08,72.03 102.08,76.89 102.31,77.11 102.31,79.97 ; 101.78,71.73 101.48,72.03 98.93,72.03 96.64,69.75 v1(96.64,68.99) ; 101.78,71.73 U20.4 ; v1(73.78,71.86) 74.51,71.13 74.51,67.85 74.77,67.59 77.78,67.59 U16.4 ; 101.27,95.97 101.27,90 98.76,87.49 98.76,86.06 99.39,85.43 101.16,85.43 103.58,83.02 103.58,80.67 103.18,80.27 102.61,80.27 102.31,79.97 ; 101.27,95.97 101.78,95.97 U22.4 ; 102.31,79.97 101.78,80.49 U21.4
  BOTTOM w0.15: v1(73.78,84.41) v1(73.78,71.86) 73.78,71.02 75.81,68.99 v1(96.64,68.99) ; v1(77.78,109.4) 77.05,109.4 76.62,108.97 61.96,108.97 61.62,109.31 v1(60.89,109.31)
MEMORY.RA2: length 226.1
  TOP w0.15: v1(76.75,86.73) 77.03,87.01 77.03,92.75 76.52,93.27 U18.3 ; U19.3 76.52,110.55 78.09,112.12 78.09,115.33 78.31,115.55 78.31,118.28 78.18,118.41 64.8,118.41 61.62,115.23 61.62,109.74 ; v1(77.03,83.68) 76.3,83.68 76.3,83.18 76.52,82.97 U17.3 ; 76.74,70.27 76.52,70.04 U16.3 ; 76.74,70.27 77.91,70.27 78.31,69.87 78.31,67.64 76.27,65.6 v1(67.74,65.6) ; 76.74,70.27 v1(76.74,71.43) ; U5.77 62.16,109.74 61.62,109.74 ; U23.3 v1(100.52,105.91) ; v1(100.52,67.16) U20.3 v1(100.52,71.3) ; 61.62,109.74 v1(61.62,104.59) ; U22.3 v1(100.52,99.8) 97.21,99.8 96.42,99 96.42,87.1 95.91,86.59 95.44,86.59 95.05,86.2 95.05,85.36 96.31,84.09 97.81,84.09 98.14,84.43 99.88,84.43 100.52,83.8 U21.3 100.52,80.41 v1(100.96,79.97)
  BOTTOM w0.15: v1(100.52,71.3) 103.03,73.81 104.55,73.81 105.06,74.32 105.06,76.33 106.96,78.23 108.55,78.23 110.14,79.82 110.14,80.58 109.25,81.47 102.46,81.47 v1(100.96,79.97) ; v1(67.74,65.6) 66.78,66.56 66.78,81.48 63.35,84.91 63.3,84.91 60.89,87.33 60.89,103.86 v1(61.62,104.59) ; v1(76.75,86.73) 76.75,84.7 77.03,84.41 v1(77.03,83.68) 77.03,82.95 76.74,82.65 v1(76.74,71.43) 78.44,69.72 97.95,69.72 v1(100.52,67.16) ; v1(100.52,105.91) v1(100.52,99.8)
MEMORY.RA3: length 149.8
  TOP w0.15: 89,73.75 88.6,74.14 77.91,74.14 75.25,71.47 v1(75.25,70.7) U16.2 ; 89,73.75 v1(91.52,73.75) ; 89,73.75 88.69,73.45 88.69,67.66 89.49,66.86 98.61,66.86 99.25,67.5 U20.2 ; v1(63.43,107.51) U5.76 ; 75.25,95.97 75.25,98.7 74.72,99.22 74.72,108.97 ; 75.25,95.97 75.65,95.97 75.77,95.84 v1(75.77,89.17) ; 75.25,95.97 U18.2 ; v1(94.44,78.09) 94.44,82.67 94.75,82.97 ; U21.2 99.25,82.97 94.75,82.97 ; 74.72,108.97 75.25,108.97 U19.2 ; 74.72,108.97 73.58,108.97 72.95,108.33 v1(72.95,107.51) ; 94.75,82.97 94.75,98.3 97.92,101.47 v1(99.03,101.47) ; U23.2 99.03,107.78 v1(99.03,106.16) ; U17.2 75.47,81.78 v1(75.47,83.4) ; U22.2 v1(99.25,98.33)
  BOTTOM w0.15: v1(75.77,89.17) 75.77,88.43 75.47,88.12 v1(75.47,83.4) 75.47,80.28 75.98,79.76 75.98,71.43 v1(75.25,70.7) ; v1(94.44,78.09) 91.52,75.16 v1(91.52,73.75) ; v1(99.03,106.16) v1(99.03,101.47) 99.03,99.28 99.25,99.06 v1(99.25,98.33) ; v1(72.95,107.51) v1(63.43,107.51)
MEMORY.RA4: length 170.2
  TOP w0.15: v1(73.97,89.51) U17.32 73.97,92.75 74.5,93.27 74.5,95.97 73.97,96.48 U18.32 v1(73.97,106.14) ; 70.75,108.97 64.99,108.97 64.74,108.71 64.74,105.89 U5.71 ; 70.75,108.97 70.75,112.7 73.93,115.87 73.97,115.87 U19.32 ; 70.75,108.97 71.05,108.67 v1(71.05,106.14) ; U21.32 97.97,92.65 v1(97.76,92.86) ; v1(98.58,79.84) 98.48,79.84 97.97,79.33 U20.32 ; v1(73.02,76.6) 73.78,76.6 73.97,76.8 U16.32 ; U23.32 97.97,115.79 97.18,115 97.12,115 95.6,113.47 v1(95.6,103.03) 97.97,103.03 U22.32
  BOTTOM w0.15: v1(73.97,106.14) v1(71.05,106.14) ; v1(98.58,79.84) 98.58,87.19 99.18,87.79 99.18,91.45 v1(97.76,92.86) 97.03,92.13 92.26,92.13 91.75,92.64 91.75,94.22 95.56,98.03 95.61,98.03 96.63,99.05 96.63,101.15 97.53,102.05 97.53,105.74 97.13,106.14 96.48,106.14 95.6,105.25 v1(95.6,103.03) 95.6,99.72 94.8,98.93 94.77,98.93 91.08,95.25 91.08,95.15 88.04,92.1 74.99,92.1 71.18,88.29 71.18,75.44 71.58,75.04 72.23,75.04 73.02,75.84 v1(73.02,76.6) 73.02,88.55 v1(73.97,89.51)
MEMORY.RA5: length 162.6
  TOP w0.15: U18.31 75.25,105.33 75.75,105.84 v1(75.76,105.84) ; U16.31 v1(75.25,76.58) ; U23.31 99.25,116 97.34,114.09 97.33,114.09 96.06,112.83 96.06,106.14 v1(96.8,105.41) 99.25,105.41 U22.31 ; U20.31 v1(99.25,76.6) ; v1(73.02,103.16) 73.02,89.23 73.91,88.34 v1(74.72,88.34) 74.72,89.38 75.25,89.9 U17.31 ; U19.31 v1(75.25,115.14) ; U5.70 64.23,104.62 64.16,104.56 v1(63.43,104.56) 62.7,105.29 v1(62.7,115.14) ; U21.31 99.25,89.76 v1(97.84,88.36)
  BOTTOM w0.15: v1(99.25,76.6) 97.84,78 v1(97.84,88.36) ; v1(75.76,105.84) 75.76,105.06 73.85,103.16 v1(73.02,103.16) 71.62,104.56 v1(63.43,104.56) ; v1(75.25,115.14) v1(62.7,115.14) ; v1(75.25,76.58) 75.25,77.32 74.72,77.84 v1(74.72,88.34) 74.72,89.19 76,90.45 92.19,90.45 94.28,88.36 v1(97.84,88.36) ; v1(97.84,88.36) 98.58,89.09 98.58,90.15 96.93,91.8 92.09,91.8 91.45,92.44 91.45,94.82 95.27,98.63 95.31,98.63 96.2,99.52 96.2,101.9 96.8,102.5 v1(96.8,105.41)
MEMORY.RA6: length 164.9
  TOP w0.15: U23.30 100.52,115.38 99.74,114.61 99.74,109.28 99.77,109.25 99.77,103.33 100.06,103.03 ; v1(71.91,84.23) 71.08,85.06 71.08,98.66 70.75,99 v1(70.75,102.35) 71.78,103.39 71.78,109.79 76.52,114.53 U19.30 ; U18.30 v1(76.52,102.35) ; U16.30 76.52,76.79 75.5,75.78 v1(71.91,75.78) ; v1(72.29,87.61) 75.37,87.61 76.52,88.75 U17.30 ; U5.69 v1(64.31,103.35) ; 100.06,103.03 100.52,103.03 U22.30 ; 100.06,103.03 100.06,101.42 99.18,100.53 97.47,100.53 95.69,98.75 v1(95.69,91.07) v1(95.69,87.45) ; v1(97.75,89.6) 97.99,89.6 98.5,90.11 98.5,92.07 99.13,92.7 100.26,92.7 100.52,92.45 U21.30 ; v1(97.75,75.87) 99.63,75.87 100.52,76.76 U20.30
  BOTTOM w0.15: v1(64.31,103.35) 69.75,103.35 v1(70.75,102.35) v1(76.52,102.35) ; v1(95.69,87.45) 97.38,85.77 97.38,76.25 v1(97.75,75.87) ; v1(71.91,75.78) v1(71.91,84.23) 71.91,84.96 72.29,85.34 v1(72.29,87.61) 72.29,88.91 74.45,91.07 v1(95.69,91.07) 97.12,91.07 97.75,90.43 v1(97.75,89.6)
MEMORY.RA7: length 181.3
  TOP w0.15: U17.29 77.78,86.29 77.48,85.99 v1(77.48,85.15) 73.64,85.15 71.48,87.31 v1(71.48,100.81) 72.21,101.54 72.21,108.59 76.15,112.53 76.2,112.53 77.78,114.12 U19.29 ; U16.29 v1(77.78,76.6) 76.56,75.38 72.81,75.38 72.48,75.04 66.25,75.04 65.78,75.51 64.59,75.51 63.95,74.88 63.95,74.16 65.09,73.01 73.55,73.01 75.01,74.48 92.18,74.48 93.52,73.15 95.33,73.15 97.32,75.14 ; U5.67 v1(64.2,100.81) ; 97.32,75.14 97.02,75.44 97.02,79.43 98.16,80.57 99.64,80.57 99.77,80.7 99.77,83.43 v1(99.49,83.7) ; 97.32,75.14 100.01,75.14 101.78,76.91 U20.29 ; U18.29 v1(77.78,100.81) ; U23.29 101.78,114.67 100.04,112.92 100.04,109.96 100.44,109.56 101.67,109.56 102.31,108.93 102.31,106.56 101.78,106.05 U22.29 101.78,98.03 102.31,97.5 102.31,93.56 101.78,93.05 U21.29 101.78,88.75 v1(99.49,86.46)
  BOTTOM w0.15: v1(64.2,100.81) v1(71.48,100.81) v1(77.78,100.81) ; v1(77.48,85.15) 77.48,84.41 77.78,84.11 v1(77.78,76.6) ; v1(99.49,86.46) v1(99.49,83.7)
MEMORY.RA8: length 140.2
  TOP w0.15: v1(79.06,84.86) U17.28 79.06,92.63 78.31,93.38 78.31,95.93 77.67,96.56 77.13,96.56 76.5,97.2 v1(76.5,99.54) 77.56,99.54 78.84,100.81 78.84,103.03 ; U19.28 79.06,115.1 78.53,114.58 78.53,103.03 78.84,103.03 ; 103.28,90.03 103.58,90.03 v1(103.58,101.11) 103.58,102.18 103.06,102.7 U22.28 ; 103.28,90.03 103.28,86.52 104.07,85.73 104.08,85.73 106.11,83.7 v1(106.11,80.14) ; 103.28,90.03 103.06,90.03 U21.28 ; v1(81.49,75.53) 80.2,75.53 79.06,76.68 U16.28 ; v1(102.83,76.27) 102.83,77.03 103.06,77.03 U20.28 ; v1(94.95,75) 94.22,75 94.01,75.21 v1(85.62,75.21) ; 78.84,103.03 79.06,103.03 U18.28 ; U5.66 v1(64.2,99.54) ; U23.28 v1(103.06,113.49)
  BOTTOM w0.15: v1(103.06,113.49) 103.06,112.76 103.58,112.24 v1(103.58,101.11) ; v1(79.06,84.86) 81.49,82.43 v1(81.49,75.53) 84.56,75.53 84.89,75.21 v1(85.62,75.21) ; v1(76.5,99.54) 75.76,99.54 v1(64.2,99.54) ; v1(106.11,80.14) 105.38,80.14 102.83,77.6 v1(102.83,76.27) 101.1,74.54 95.42,74.54 v1(94.95,75)
MEMORY.RA9: length 274.3
  TOP w0.15: v1(110.42,76.48) 110.67,76.73 U20.22 110.67,79.41 109.07,79.41 108.67,79.8 108.67,82.87 108.87,83.06 108.87,87.03 109.27,87.42 109.32,87.42 110.46,88.57 v1(110.46,89.6) 110.46,91.22 U21.22 ; v1(47.66,118.3) 47.66,109.7 59.09,98.27 v1(64.31,98.27) U5.65 ; U23.22 110.67,116.03 112.58,114.13 v1(117.65,114.13) 117.65,109.77 117.15,109.27 114.37,109.27 113.73,108.63 113.73,106.72 112.72,105.7 110.93,105.7 110.67,105.45 U22.22 v1(110.67,100.97) ; v1(86.39,76.6) 86.67,76.89 U16.22 ; U17.22 86.67,89.85 v1(87.12,89.4) ; U18.22 86.67,102.27 85.66,101.25 v1(84.88,101.25) 82.84,101.25 81.06,103.03 81.06,107.66 80.84,107.88 80.84,109.59 79.7,110.73 79.63,110.73 79.12,111.24 79.12,112.01 80.64,113.53 85.41,113.53 86.67,114.8 U19.22
  BOTTOM w0.15: v1(117.65,114.13) 117.65,115 114.35,118.3 v1(47.66,118.3) ; v1(110.67,100.97) 110.67,100.23 111.19,99.71 111.19,90.33 v1(110.46,89.6) ; v1(87.12,89.4) 87.12,76.6 ; 87.12,76.6 87.12,73.22 85.94,72.04 85.94,71.2 86.58,70.56 101.24,70.56 102.46,71.79 109.41,71.79 110.42,72.81 v1(110.42,76.48) ; 87.12,76.6 v1(86.39,76.6) ; v1(84.88,101.25) 84.88,102.98 80.69,107.17 80.09,107.17 78.82,105.9 78.82,100.69 76.79,98.66 66.14,98.66 65.74,98.27 v1(64.31,98.27)
MEMORY.RA10: length 237.2
  TOP w0.15: U5.64 64.74,97 64.44,96.7 ; 64.44,96.7 64.44,94.52 65.23,93.72 67.56,93.72 68.19,93.09 v1(68.19,92.11) ; 64.44,96.7 v1(52.24,96.7) ; 88.69,118.41 87.94,118.41 U19.21 ; 88.69,118.41 88.69,116.04 88.78,115.96 88.78,111.69 v1(87.42,110.34) 87.42,103.03 87.72,103.03 ; 88.69,118.41 111.94,118.41 U23.21 111.94,116.01 113.09,114.87 v1(114.6,114.87) ; U16.21 87.94,79.45 87.69,79.7 81.38,79.7 81.08,79.41 68.98,79.41 68.55,78.97 v1(67.82,78.97) ; U20.21 111.94,79.41 111.73,79.62 111.73,79.65 112.24,80.16 v1(112.47,80.16) 112.47,83.91 111.94,84.42 U21.21 ; 87.72,103.03 87.94,103.03 U18.21 ; 87.72,103.03 87.72,102.69 83.53,98.5 83.11,98.5 81.08,96.47 81.08,93.7 81.47,93.31 81.48,93.31 82.12,92.67 82.12,90.31 83.77,88.66 87.44,88.66 87.94,89.17 U17.21 ; v1(112.68,99.24) 111.94,99.97 U22.21
  BOTTOM w0.15: v1(52.24,96.7) 52.24,109.07 54.02,110.85 85.51,110.85 86.02,110.34 v1(87.42,110.34) ; v1(68.19,92.11) 68.19,91.38 67.82,91.01 v1(67.82,78.97) ; v1(114.6,114.87) 114.6,115.7 113.97,116.33 113.1,116.33 112.7,115.94 112.7,101.49 113.41,100.78 113.41,99.97 v1(112.68,99.24) 112.68,98.5 112.47,98.29 v1(112.47,80.16)
MEMORY.RA11: length 224.4
  TOP w0.15: U18.20 89.22,103.03 88.69,103.03 ; U5.63 67.84,95.73 69.75,93.83 69.75,91.38 v1(69.02,90.65) ; v1(70.15,77.54) 67.93,77.54 66.79,78.68 66.79,79.2 67.29,79.7 80.78,79.7 81.08,80 88.71,80 89.22,79.5 U16.20 89.02,78.22 v1(89.02,76.6) ; U19.20 89.22,109.83 88.69,109.31 88.69,103.03 ; U20.20 v1(113.22,76.6) ; U22.20 113.22,103.03 113.44,102.81 v1(113.44,102.02) ; U21.20 v1(113.22,88.85) ; 88.69,103.03 v1(88.69,102.3) ; v1(113.44,115.6) 113.44,117.22 U23.20 ; U17.20 v1(89.22,89.42)
  BOTTOM w0.15: v1(89.22,89.42) 89.22,77.53 89.02,77.33 v1(89.02,76.6) ; v1(113.44,115.6) v1(113.44,102.02) 113.71,101.74 113.71,94.33 113.22,93.83 v1(113.22,88.85) v1(113.22,76.6) 113.22,70.77 110.04,67.59 109.94,67.59 107.65,65.31 72.18,65.31 70.15,67.34 v1(70.15,77.54) 70.15,89.52 v1(69.02,90.65) 69.02,92.44 68.19,93.26 68.19,93.92 68.59,94.32 87.3,94.32 88.69,95.72 v1(88.69,102.3)
